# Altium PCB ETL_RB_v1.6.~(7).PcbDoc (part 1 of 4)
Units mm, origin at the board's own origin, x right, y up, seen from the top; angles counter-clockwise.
Board outline 130.3 x 56.5 mm, 8 copper layers (Top Layer, plane 1, M1, plane 2, plane 3, M2, plane 4, Bottom Layer), stack 0.937 mm thick; 215 components, 190 nets, 1969 pads, 914 vias.
Unrouted connection lines stored in the file: 395.
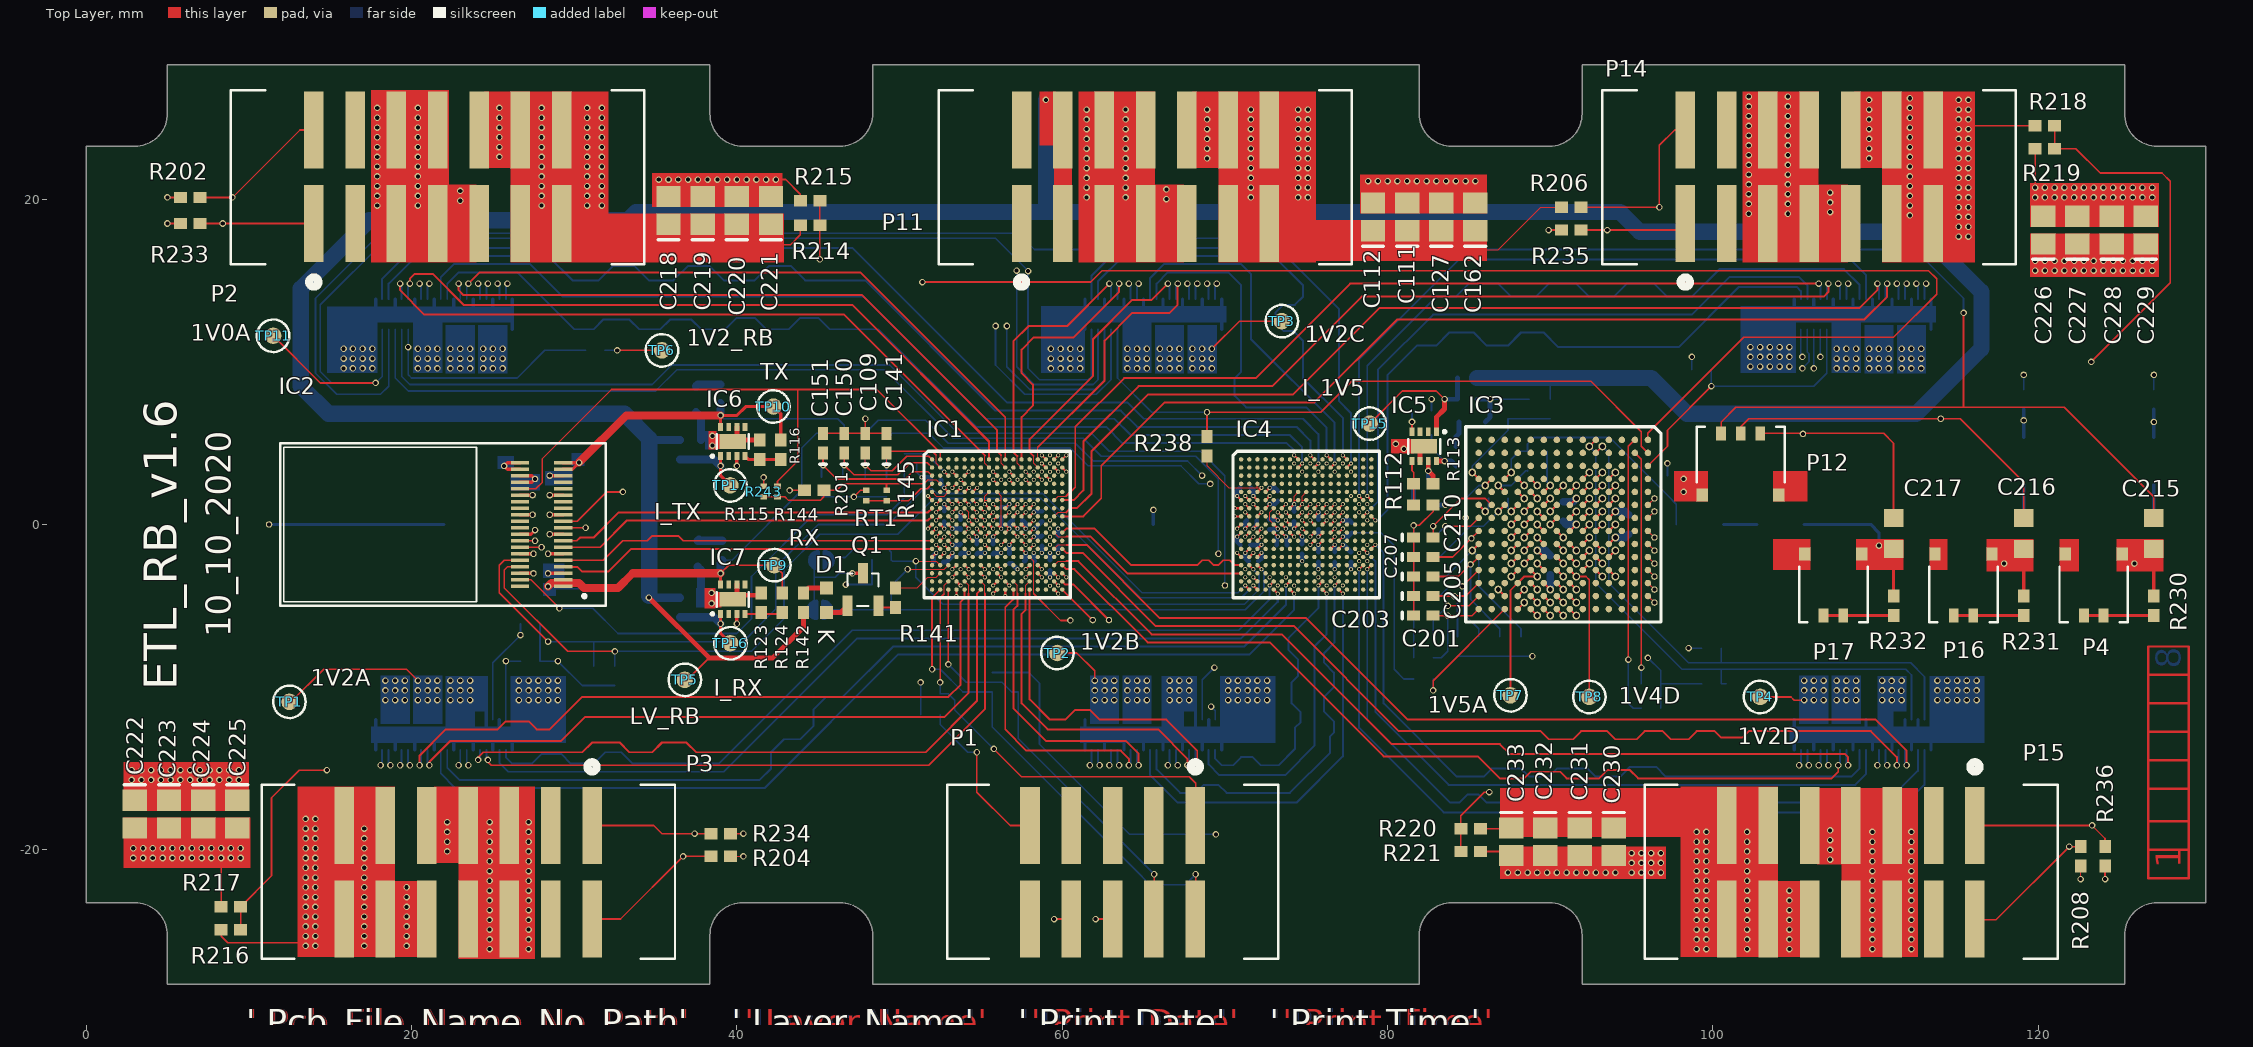
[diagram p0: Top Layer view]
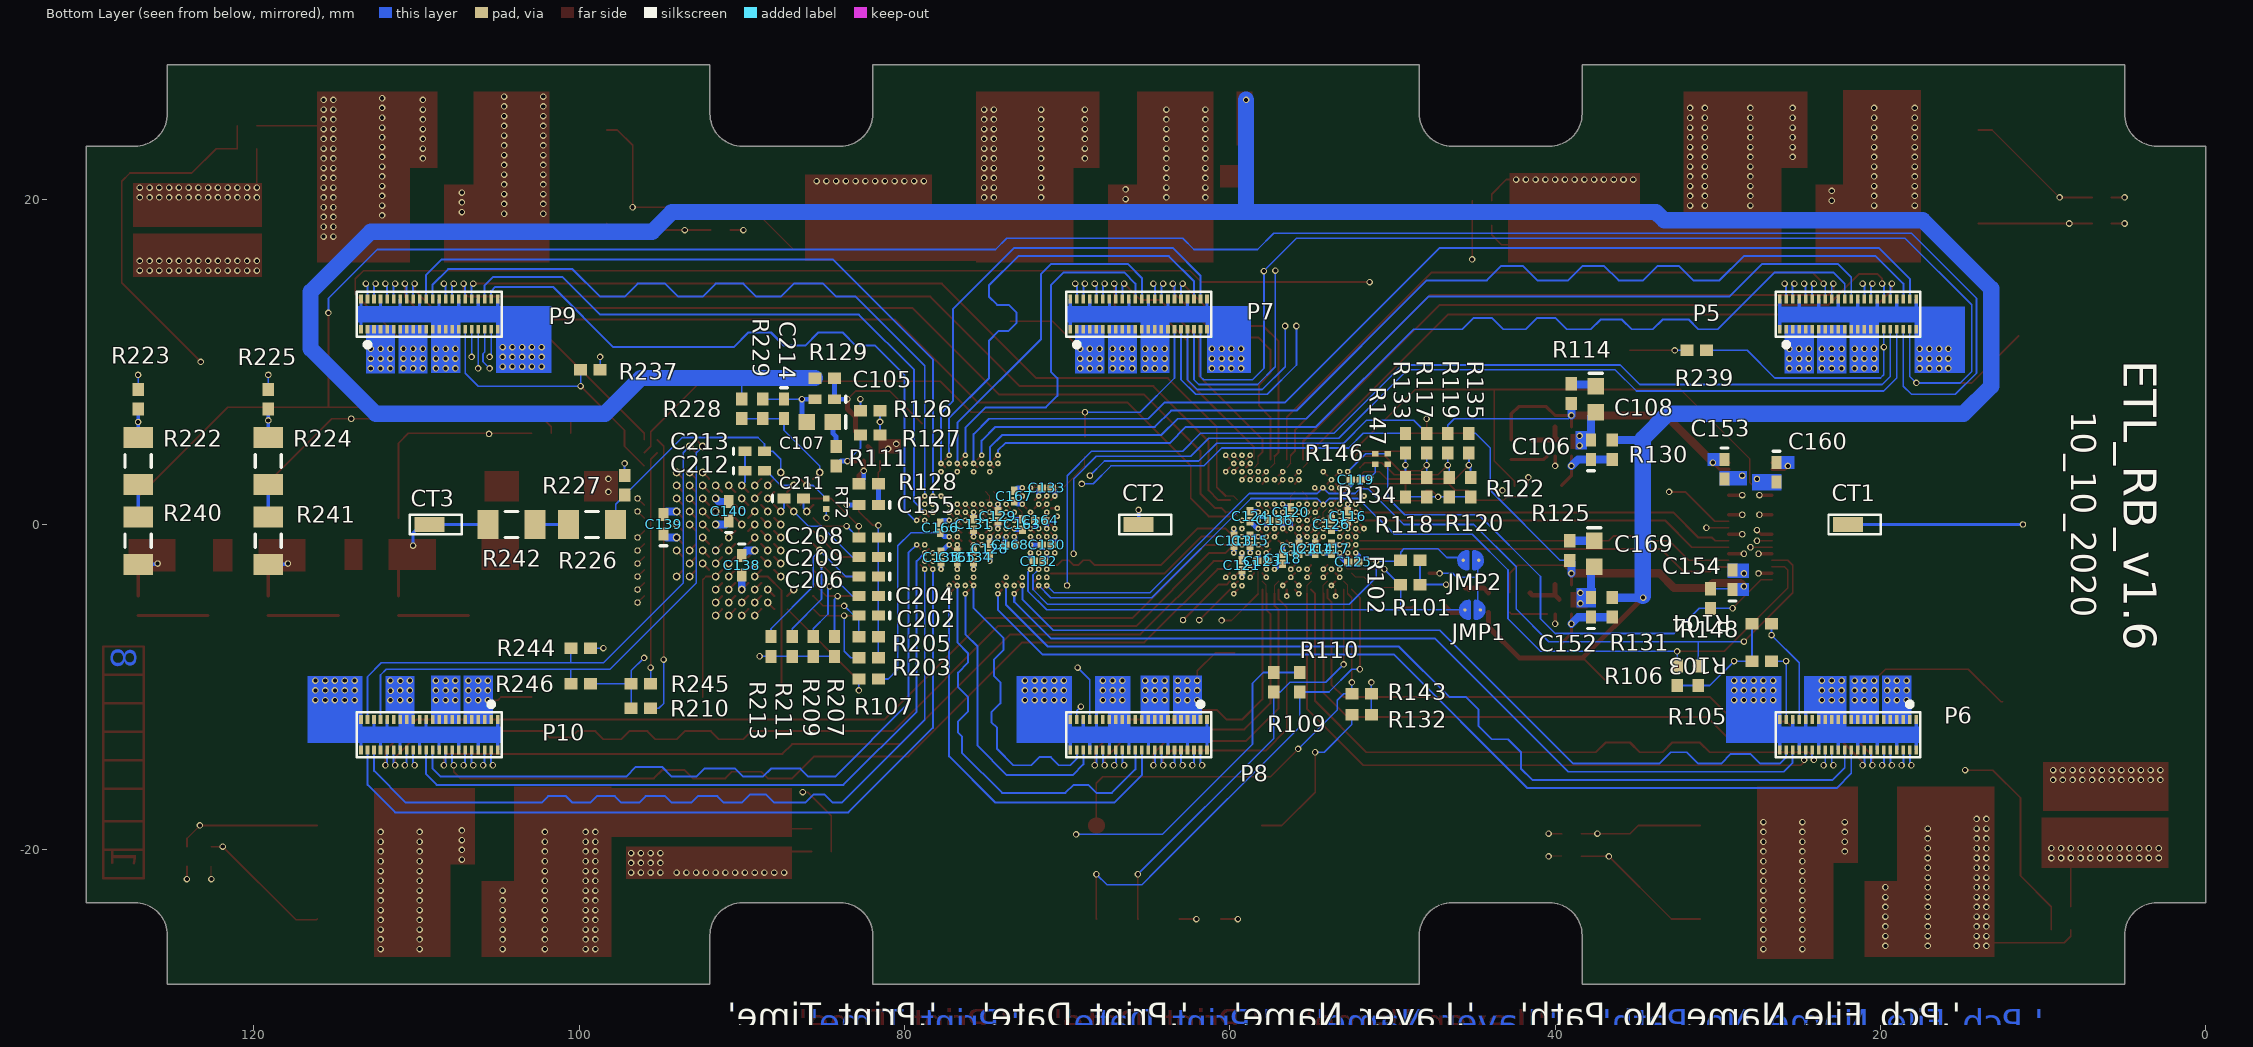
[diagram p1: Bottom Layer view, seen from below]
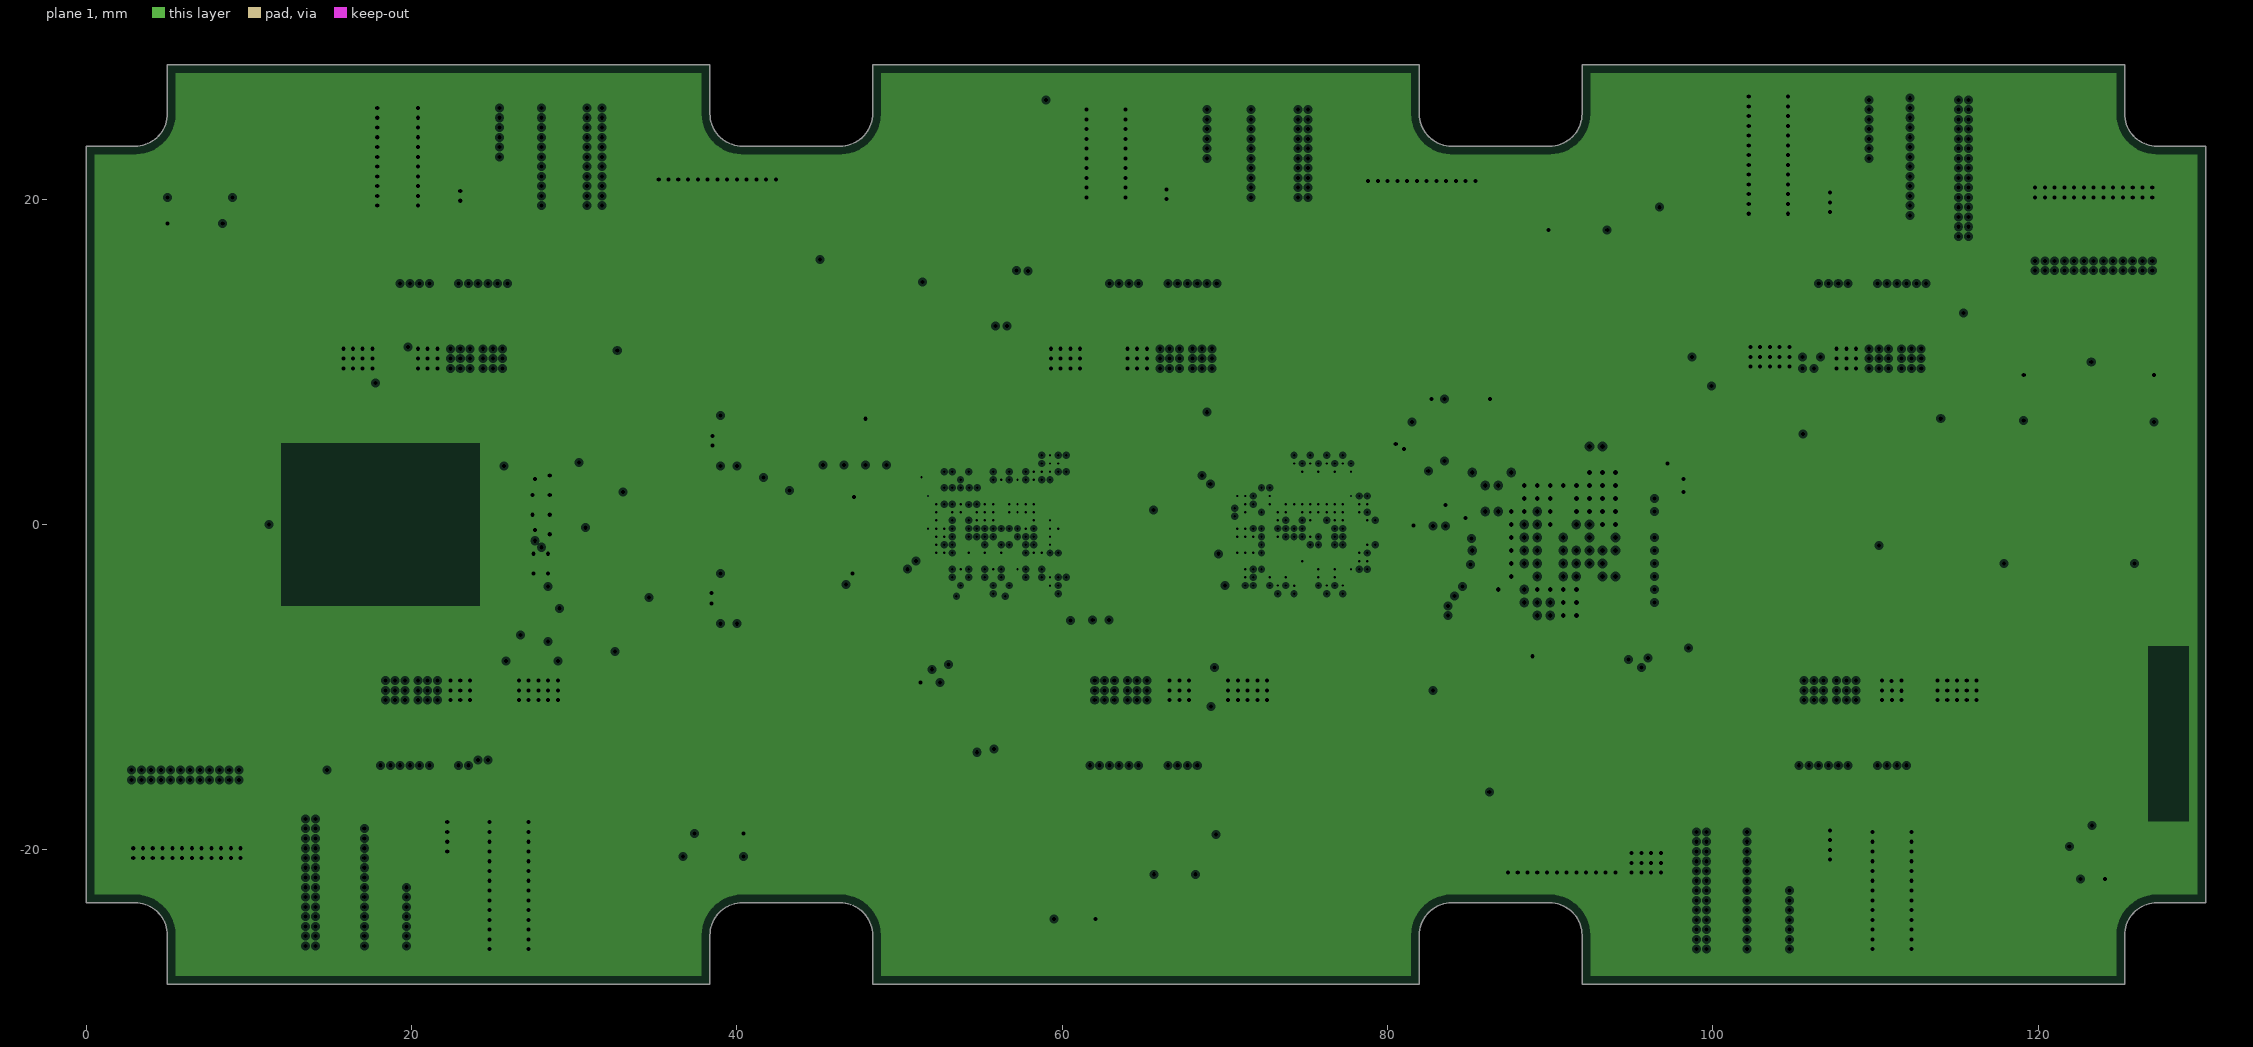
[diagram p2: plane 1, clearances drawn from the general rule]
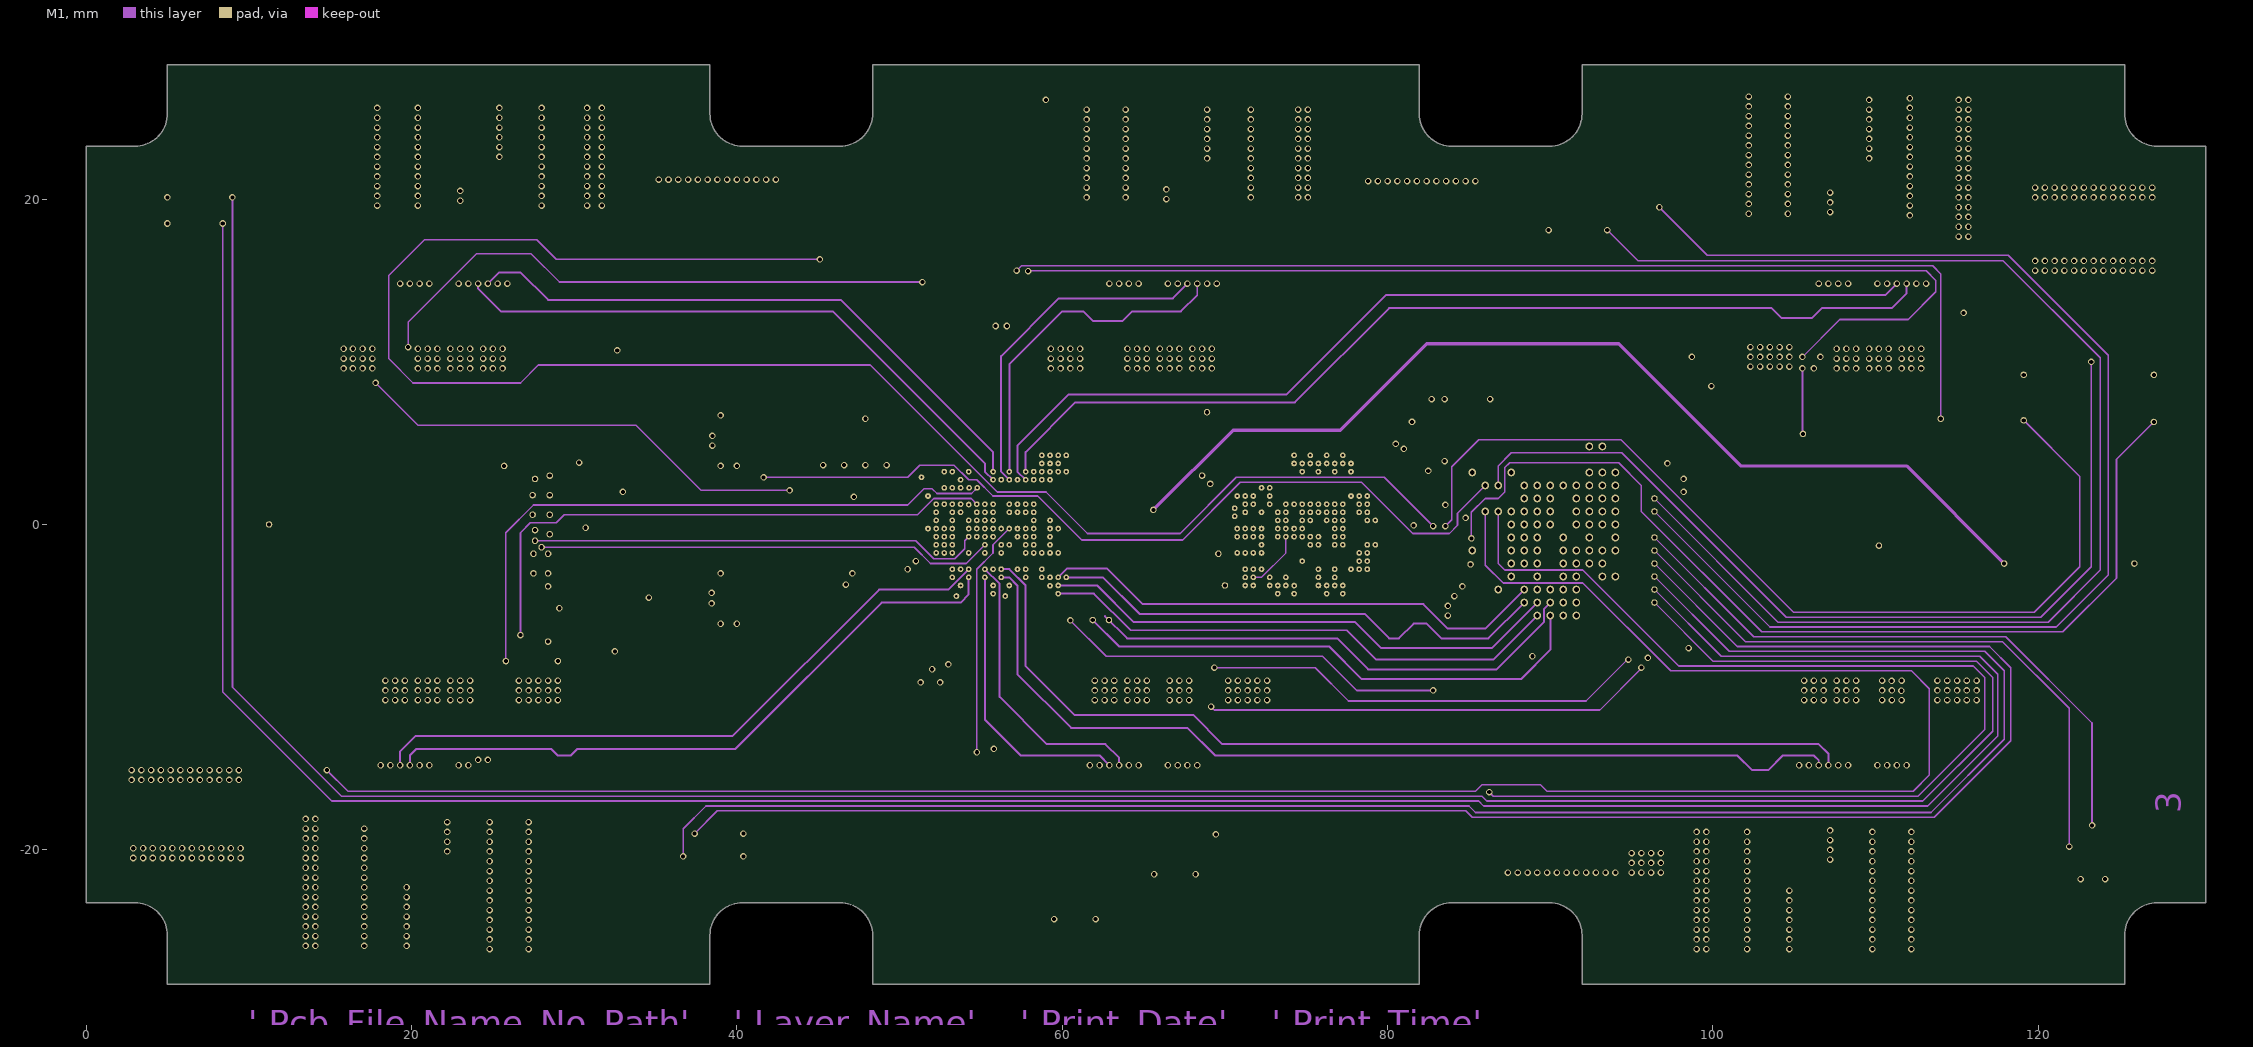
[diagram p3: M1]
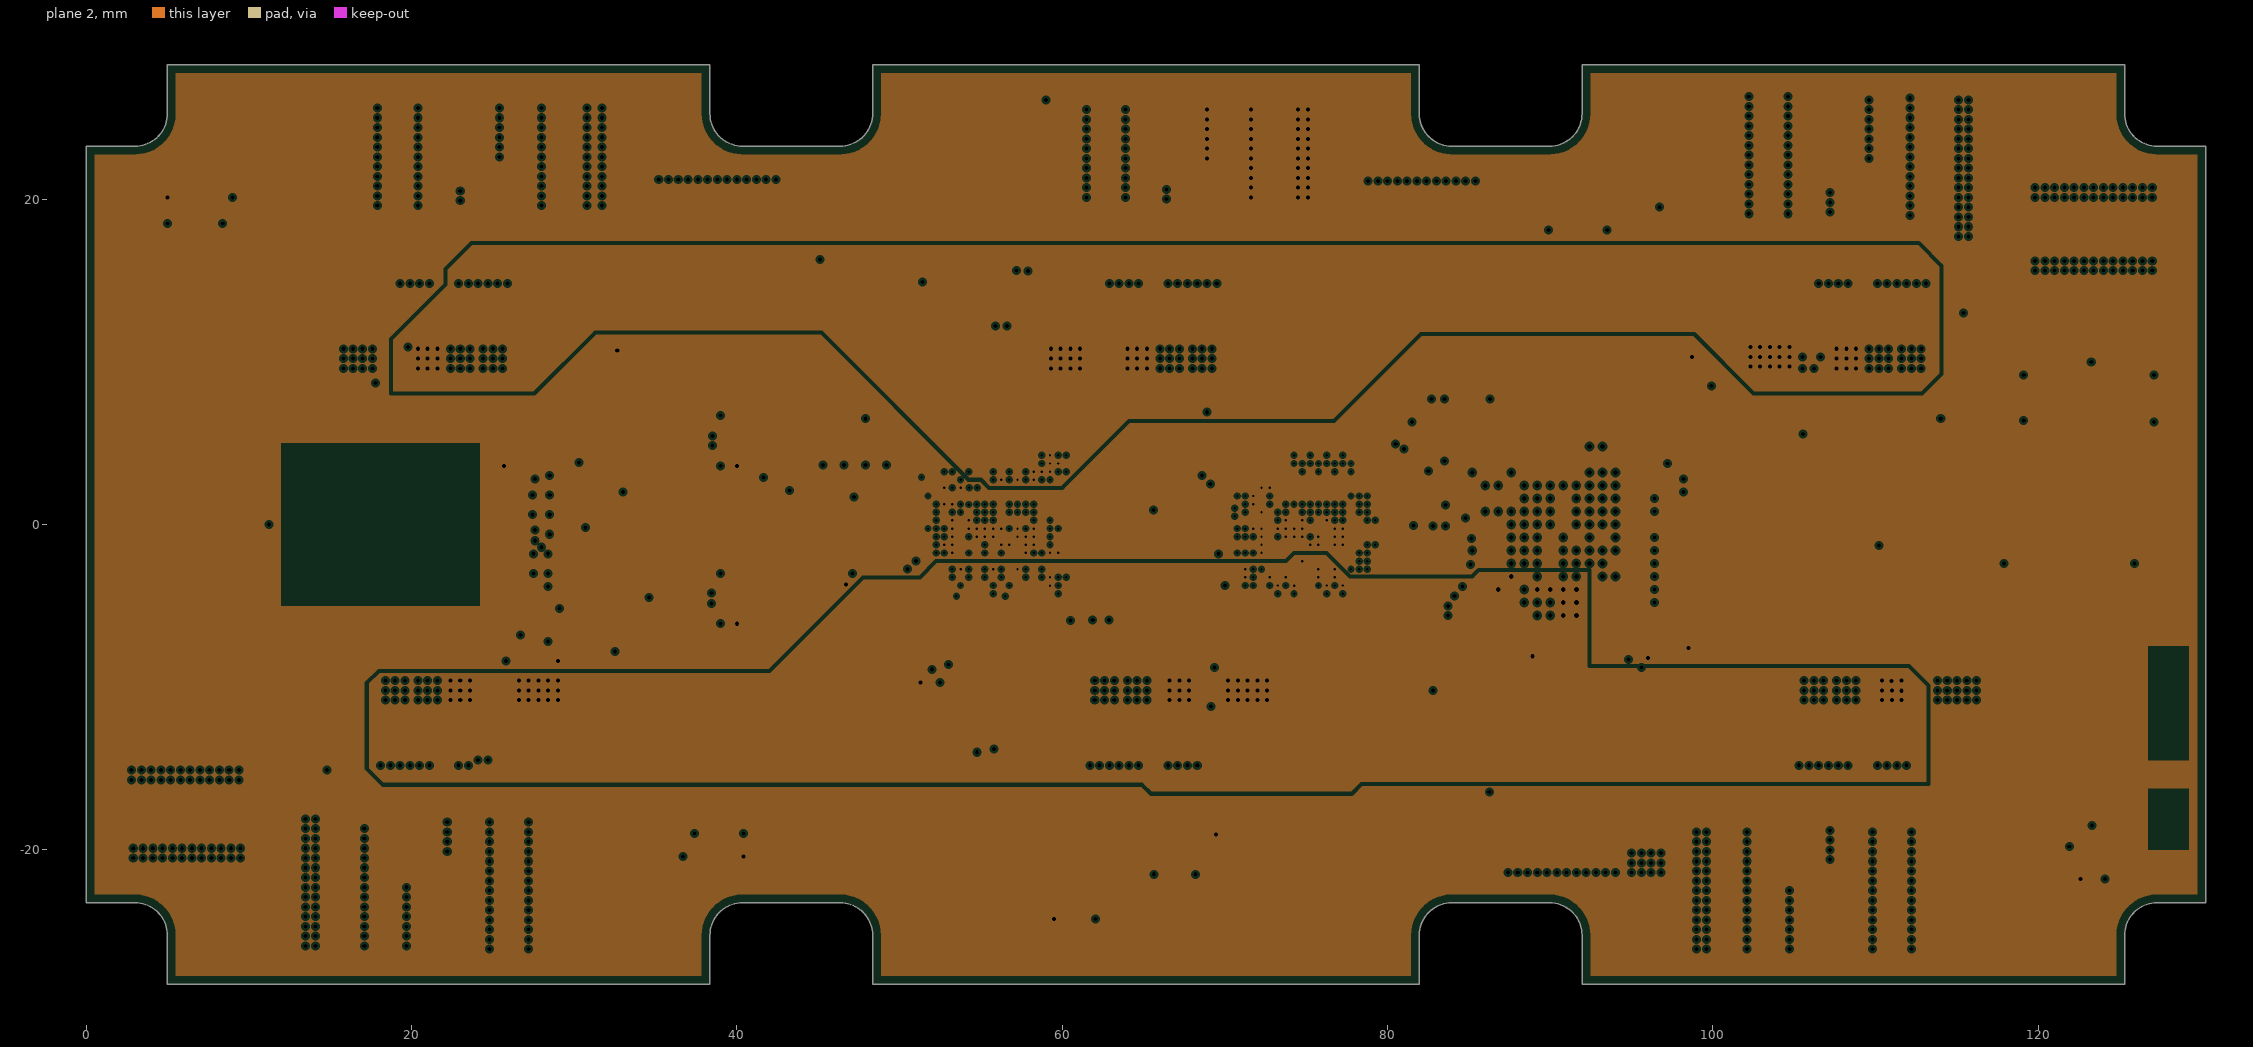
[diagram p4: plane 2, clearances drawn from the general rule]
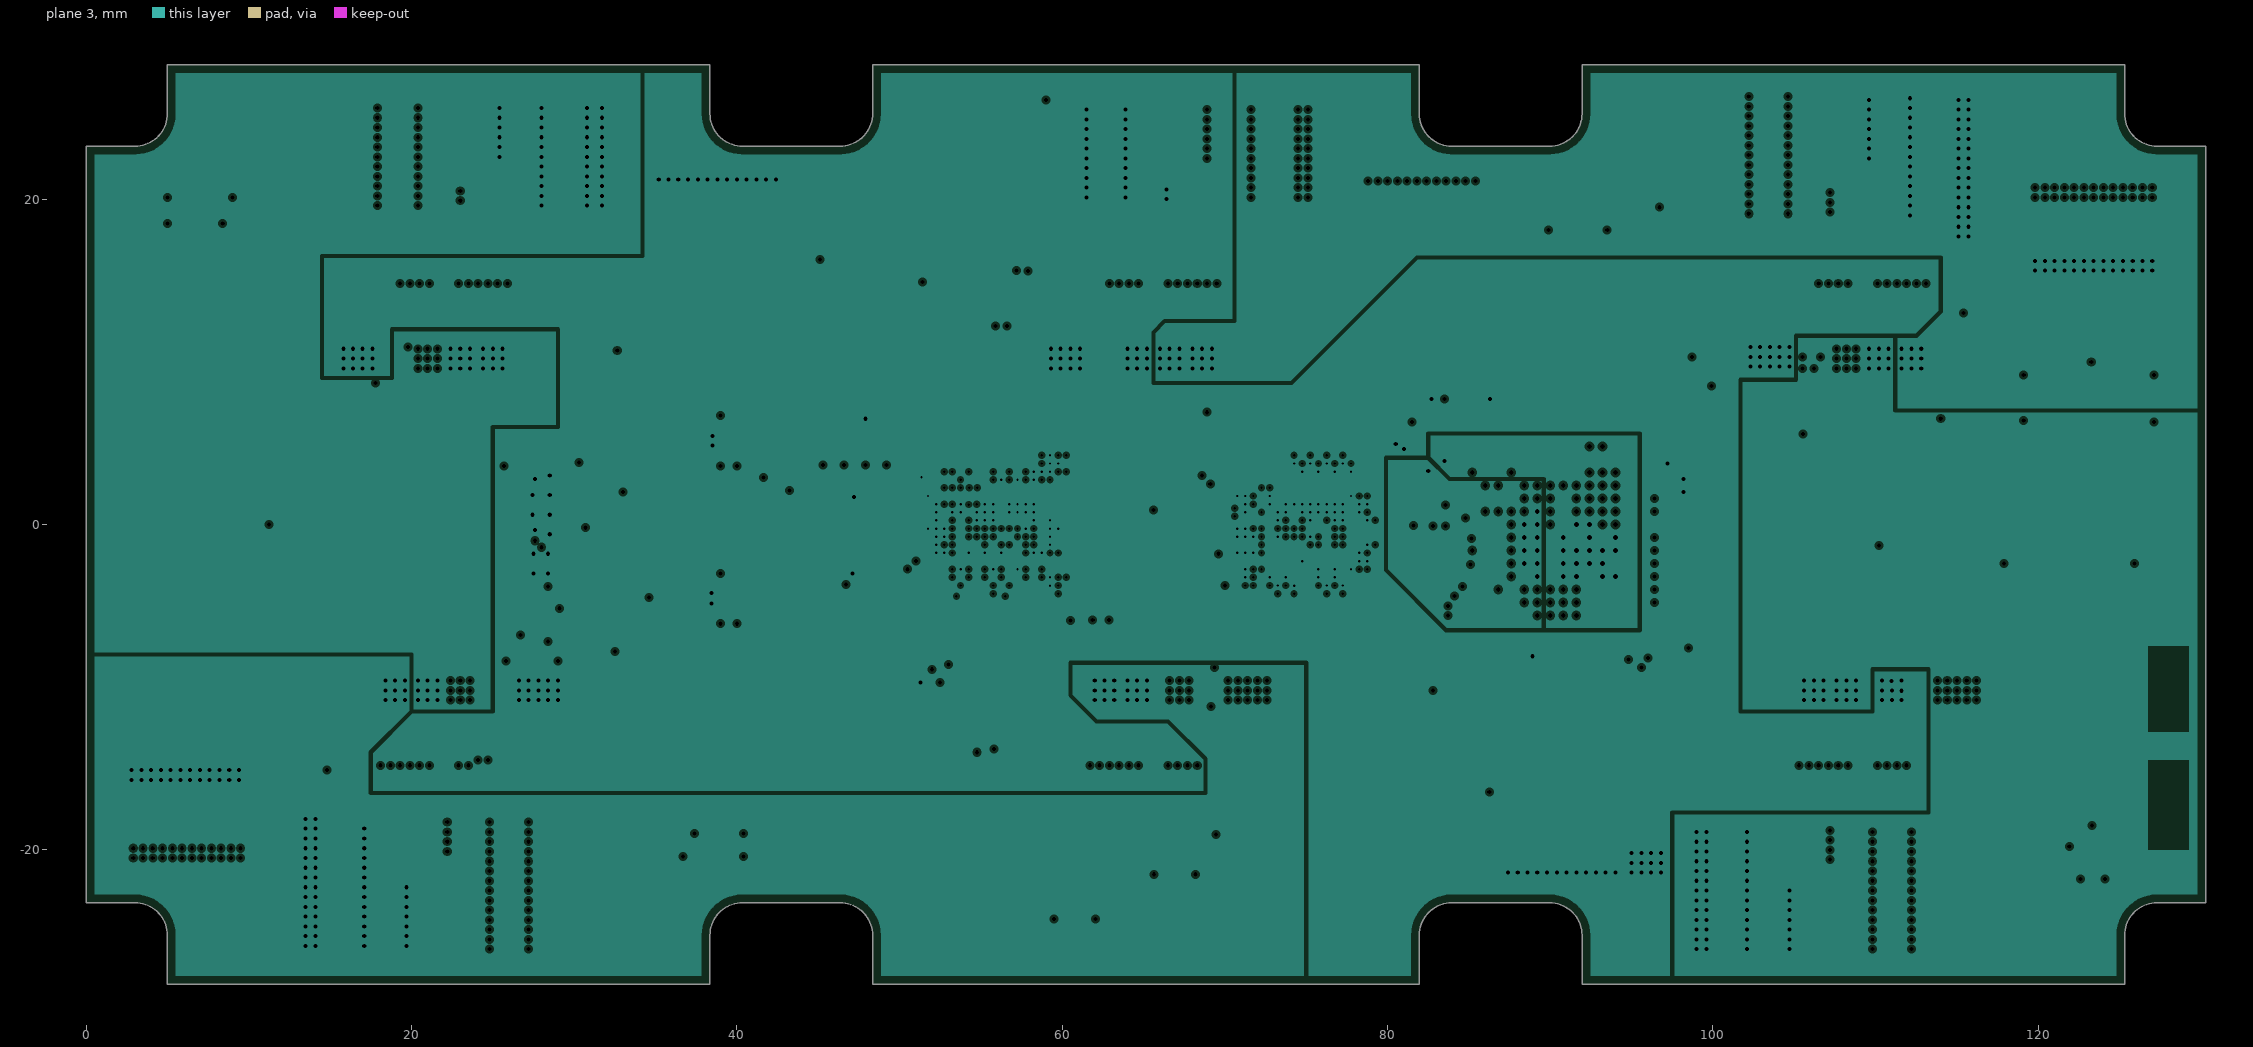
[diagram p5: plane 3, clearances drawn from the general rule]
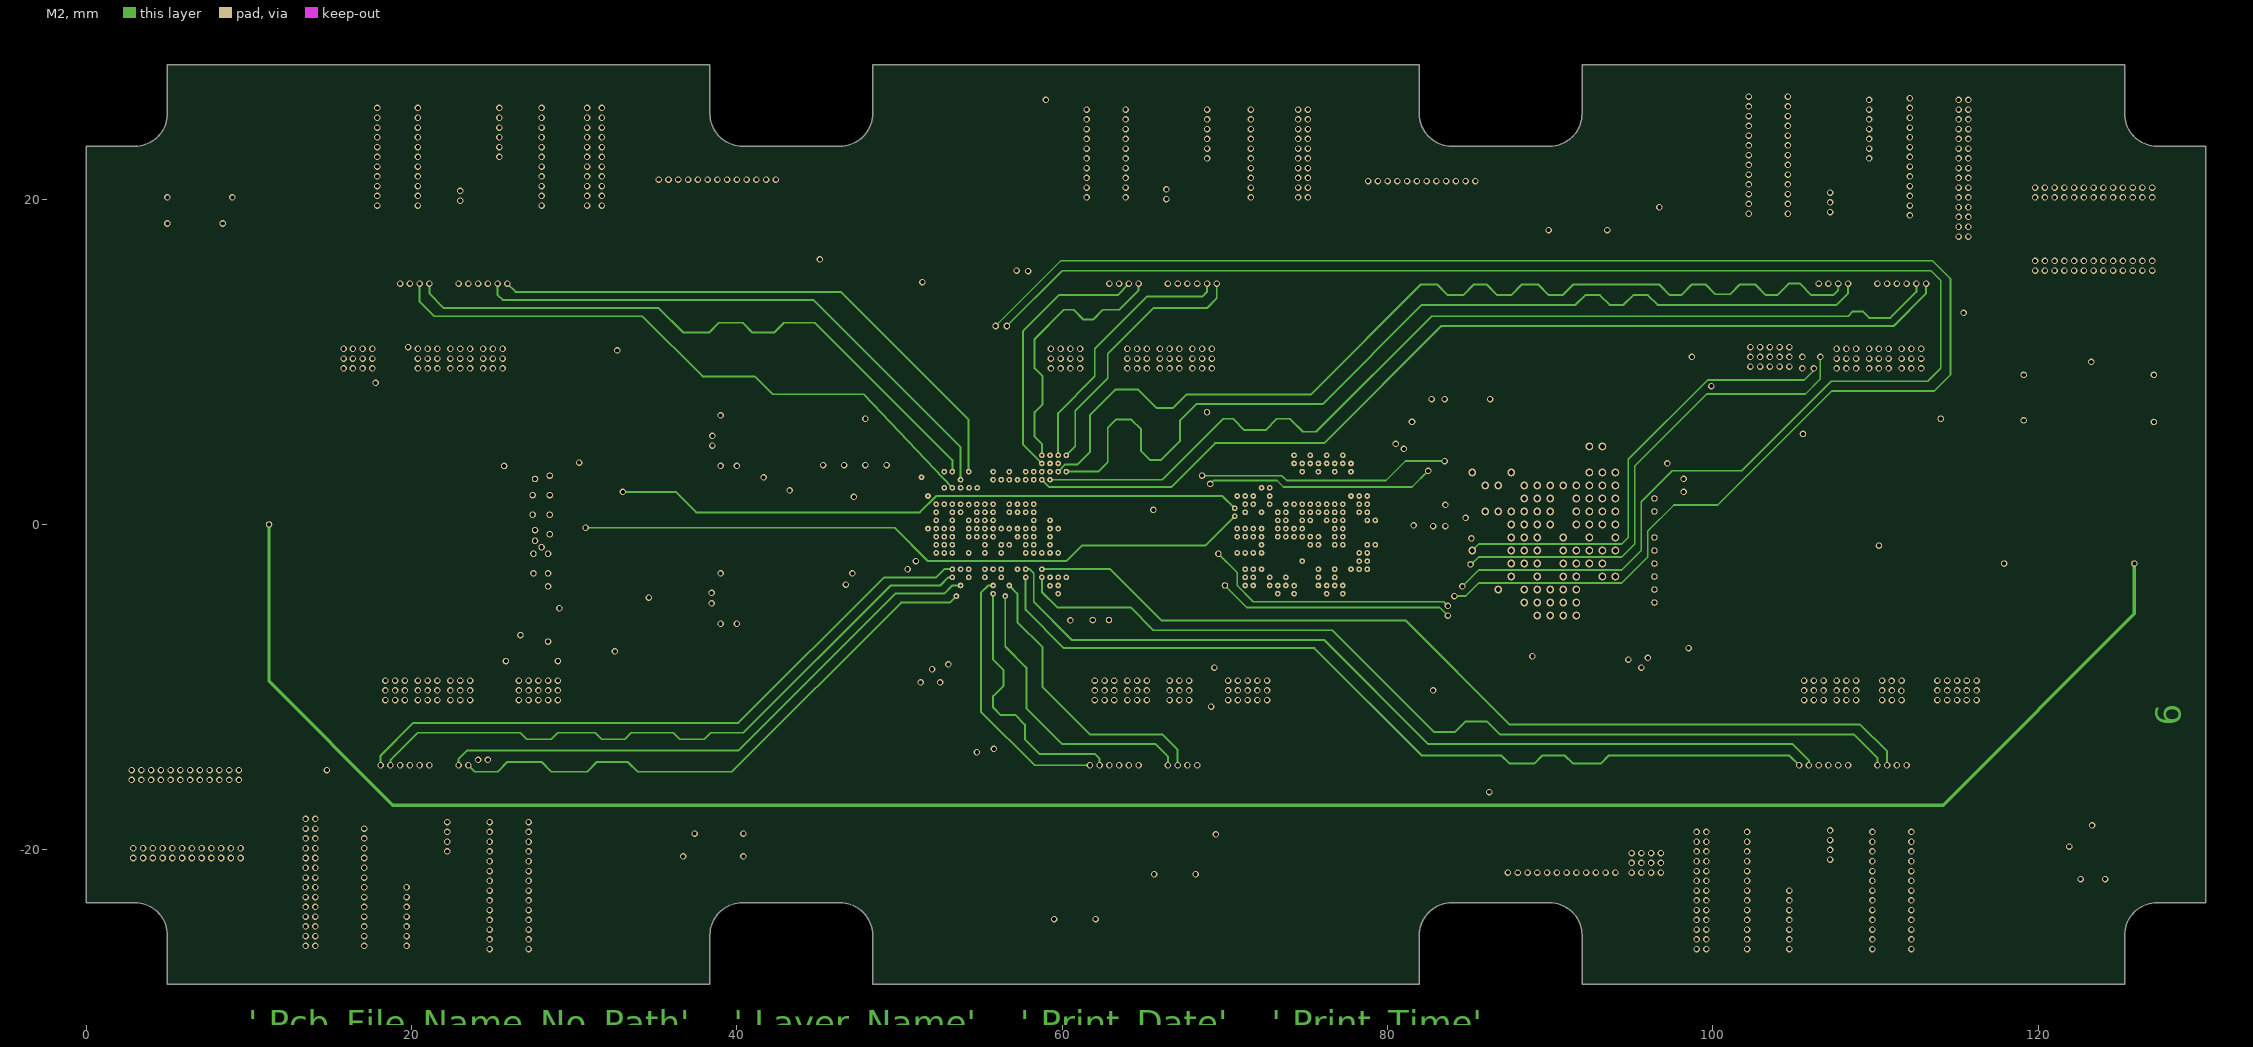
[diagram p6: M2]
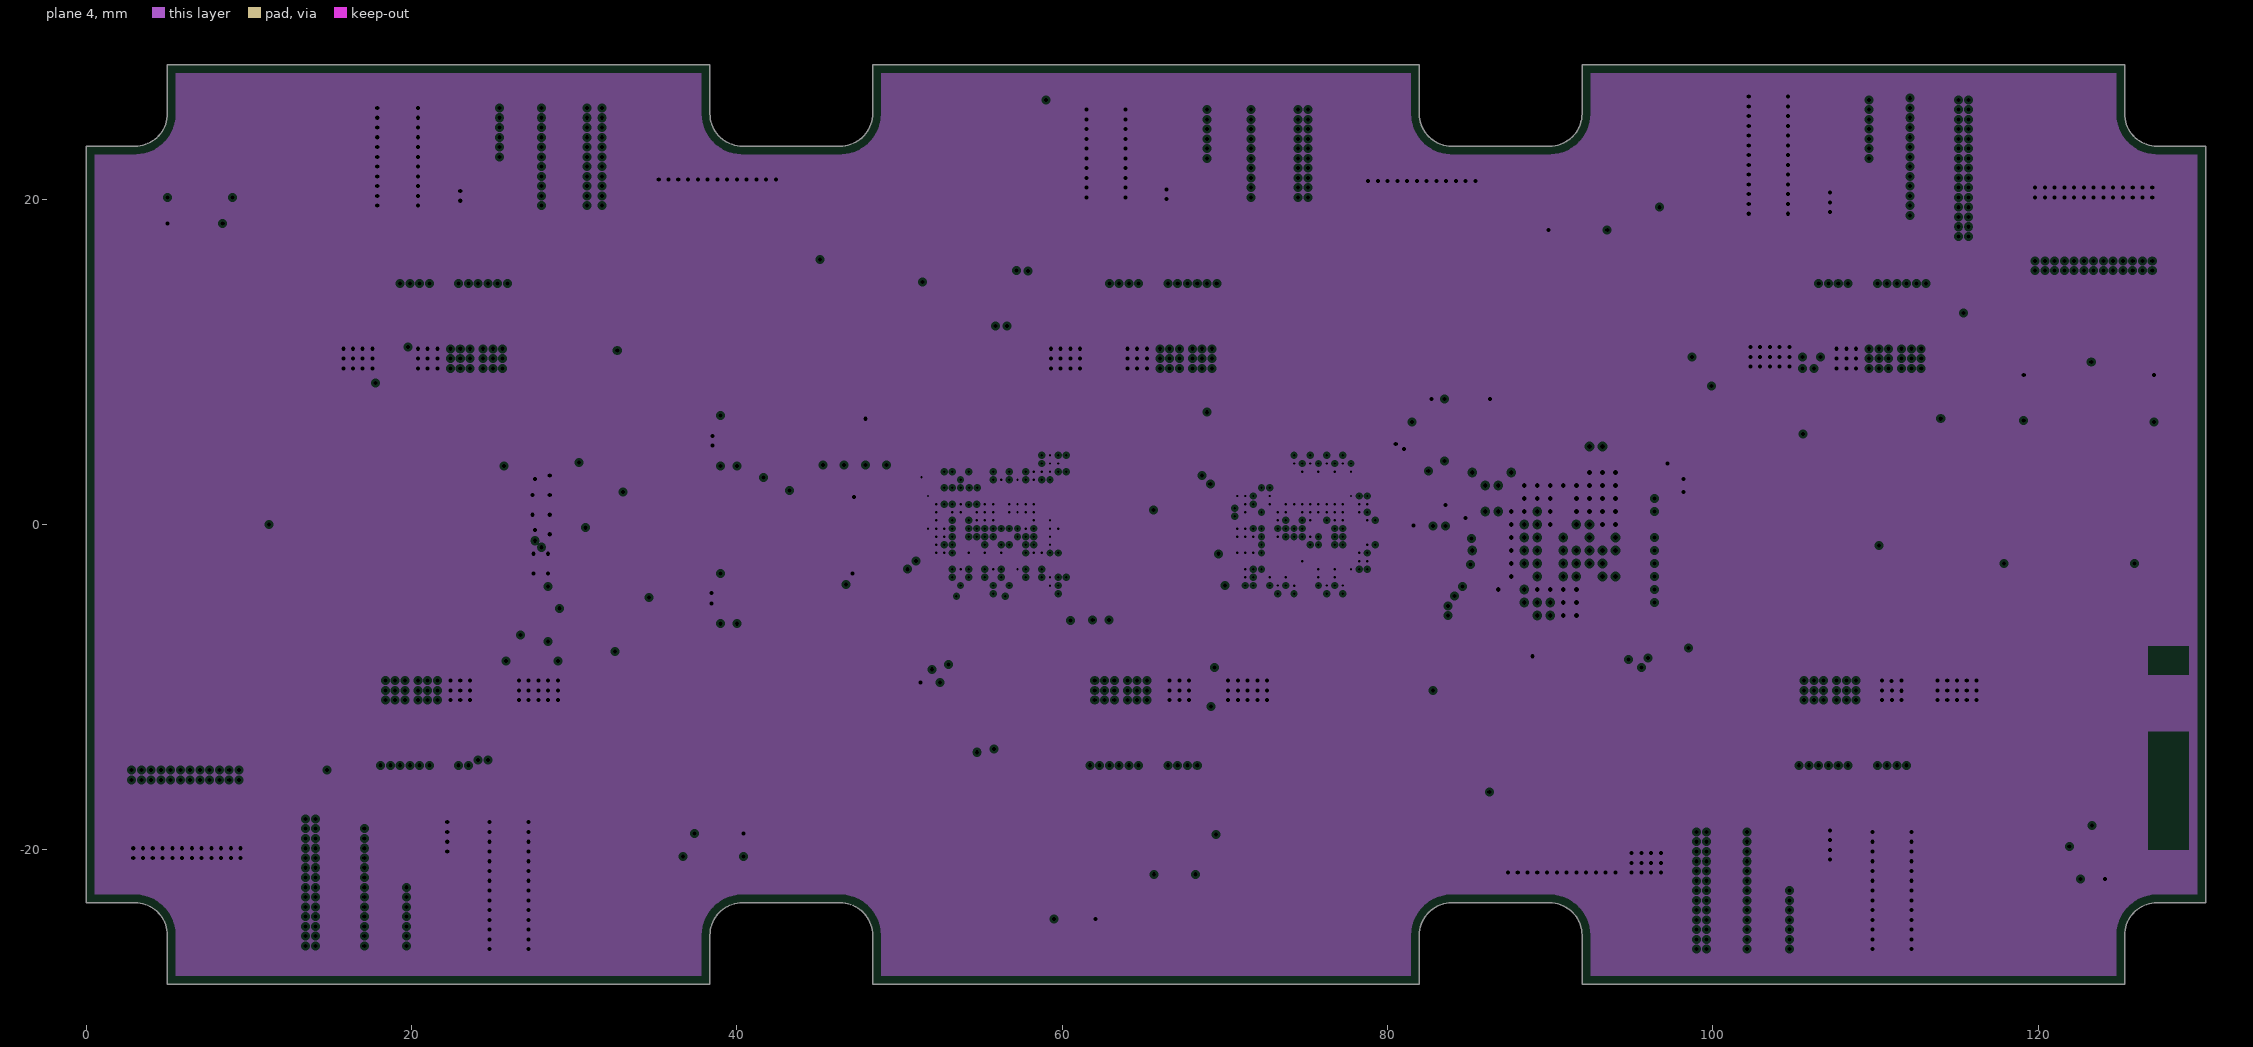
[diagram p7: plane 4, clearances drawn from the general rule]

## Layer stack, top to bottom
Top Solder: solder mask 0.0178, Solder Resist, Dk 4.1
Top Layer: signal copper 0.0175
Dielectric 1: prepreg 0.0691, 1080, Dk 3.4
plane 1: plane copper 0.035, net GND
Dielectric 2: core 0.1016, TU-863, Dk 3.7
M1: signal copper 0.018
Dielectric 3: prepreg 0.1417, 1080, Dk 3.4
plane 2: plane copper 0.035, net (Multiple Nets)
Dielectric 4: core 0.1016, TU-863, Dk 3.7
plane 3: plane copper 0.035, net (Multiple Nets)
Dielectric 5: prepreg 0.1417, 1080, Dk 3.4
M2: signal copper 0.018
Dielectric 6: core 0.1016, TU-863, Dk 3.7
plane 4: plane copper 0.035, net GND
Dielectric 7: prepreg 0.0691, 1080, Dk 3.4
Bottom Layer: signal copper 0.0175
Bottom Solder: solder mask 0.0178, Solder Resist, Dk 4.1

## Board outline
5,-28.25 5,-25.25 ccw(c3,-25.25) 3,-23.25 0,-23.25 0,23.25 3,23.25 ccw(c3,25.25) 5,25.25 5,28.25 38.35,28.25 38.35,25.25 ccw(c40.35,25.25) 40.35,23.25 46.35,23.25 ccw(c46.35,25.25) 48.35,25.25 48.35,28.25 81.95,28.25 81.95,25.25 ccw(c83.95,25.25) 83.95,23.25 89.95,23.25 ccw(c89.95,25.25) 91.95,25.25 91.95,28.25 125.3,28.25 125.3,25.25 ccw(c127.3,25.25) 127.3,23.25 130.3,23.25 130.3,-23.25 127.3,-23.25 ccw(c127.3,-25.25) 125.3,-25.25 125.3,-28.25 91.95,-28.25 91.95,-25.25 ccw(c89.95,-25.25) 89.95,-23.25 83.95,-23.25 ccw(c83.95,-25.25) 81.95,-25.25 81.95,-28.25 48.35,-28.25 48.35,-25.25 ccw(c46.35,-25.25) 46.35,-23.25 40.35,-23.25 ccw(c40.35,-25.25) 38.35,-25.25 38.35,-28.25

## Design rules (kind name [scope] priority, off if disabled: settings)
Clearance [All] p1: gap=0.076 ignorepadtopadclearanceinfootprint=FALSE except(0: Arc-Hole Track-Hole SMDPad-Hole THPad-Hole Via-Hole Fill-Hole Poly-Hole Region-Hole Text-Hole)
Height [All] p1 off: minheight=0 maxheight=25.4 prefheight=12.7
HoleToHoleClearance HoleToHoleClearance_1 [InNet('GND') or InNet('LV_RB') or InNet('1V5A') or InNet('1V5D') or InNet('1V2A') or InNet('1V2B') or InNet('1V2C') or InNet('1V2D') vs InNet('GND') or InNet('LV_RB') or InNet('1V5A') or InNet('1V5D') or InNet('1V2A') or InNet('1V2B') or InNet('1V2C') or InNet('1V2D')] p1: gap=0.15 allowstackedmicrovias=TRUE
HoleToHoleClearance [All] p2: gap=0.254 allowstackedmicrovias=TRUE
MinimumSolderMaskSliver [All] p1: minsoldermaskwidth=0.102
PlaneClearance PlaneClearance_1 [InNetClass('BV')] p1: clearance=0.508
PlaneClearance [All] p2: clearance=0.152
PlaneConnect PlaneConnect_1 [All] p1: planeconnectstyle=Direct reliefexpansion=0.508 reliefentries=4 reliefconductorwidth=0.254 reliefairgap=0.254
PolygonConnect [All] p1: connectstyle=Relief reliefconductorwidth=0.254 reliefentries=4 polygonreliefangle="90 Angle" airgapwidth=0.254
RoomDefinition WP7B [InComponentClass('WP7B')] p1 off: confinementstyle=ConfineIn formatcopy=TRUE lockcomponents=FALSE outline 192.75,16.8 613.75,16.8 613.75,46.8 192.75,46.8
RoomDefinition lpGBT [InComponentClass('lpGBT')] p2 off: confinementstyle=ConfineIn formatcopy=TRUE lockcomponents=FALSE outline 192,-36.75 1047,-36.75 1047,-1.75 192,-1.75
RoutingVias [All] p1: holewidth=0.25 width=0.4 viastyle="Through Hole" minholewidth=0.15 minwidth=0.25 maxholewidth=0.711 maxwidth=1.27
SilkToSilkClearance [All] p1: silktosilkclearance=0.025
SilkToSolderMaskClearance [IsPad] p1: minsilkscreentomaskgap=0.025 clearancetoexposedcopper=TRUE
SolderMaskExpansion SolderMaskExpansion_1 [InPadClass('WP7B40PAD')] p1: expansion=0.038 istentingtop=FALSE
SolderMaskExpansion [All] p2: expansion=0.051 istentingtop=FALSE
Width Width_HS [InNetClass('HS')] p1: maxlimit=0.13 minlimit=0.076 preferedwidth=0.12 midlayer1_minwidth=0.12 midlayer1_maxwidth=0.12 midlayer2_minwidth=0.12 midlayer2_maxwidth=0.12 bottomlayer_minwidth=0.12 bottomlayer_maxwidth=0.12 minimp=50.000000 maximp=50.000000 favimp=50.000000 // impedance controlled signals
Width [All] p2: maxlimit=2.54 minlimit=0.076 preferedwidth=0.12 toplayer_minwidth=0.076 midlayer1_minwidth=0.076 minimp=50.000000 maximp=50.000000 favimp=50.000000
23 further rules are at their usual default settings.

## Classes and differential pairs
pad class WP7B40PAD: IC2-1 IC2-2 IC2-3 IC2-4 IC2-5 IC2-6 IC2-7 IC2-8 IC2-9 IC2-10 IC2-11 IC2-12 IC2-13 IC2-14 IC2-15 IC2-16 IC2-17 IC2-18 IC2-19 IC2-20 IC2-21 IC2-22 IC2-23 IC2-24 IC2-25 IC2-26 IC2-27 IC2-28 IC2-29 IC2-30 IC2-31 IC2-32 IC2-33 IC2-34 IC2-35 IC2-36 IC2-37 IC2-38 IC2-39 IC2-40 IC5-1 IC5-2 IC5-3 IC5-4 IC5-5 IC5-6 IC5-7 IC5-8 IC5-9 IC6-1 IC6-2 IC6-3 IC6-4 IC6-5 IC6-6 IC6-7 IC6-8 IC6-9 IC7-1 IC7-2 IC7-3 IC7-4 IC7-5 IC7-6 IC7-7 IC7-8 IC7-9 P5-1 P5-2 P5-3 P5-4 P5-5 P5-6 P5-7 P5-8 P5-9 P5-10 P5-11 P5-12 P5-13 P5-14 P5-15 P5-16 P5-17 P5-18 P5-19 P5-20 P5-21 P5-22 P5-23 P5-24 P5-25 P5-26 P5-27 P5-28 P5-29 P5-30 P5-31 P5-32 P5-33 P5-34 P5-35 P5-36 P5-37 P5-38 P5-39 P5-40 P5-41 P5-42 P5-43 P5-44 P6-1 P6-2 P6-3 P6-4 P6-5 P6-6 P6-7 P6-8 P6-9 P6-10 P6-11 P6-12 P6-13 P6-14 P6-15 P6-16 P6-17 P6-18 P6-19 P6-20 P6-21 P6-22 P6-23 P6-24 P6-25 P6-26 P6-27 P6-28 P6-29 P6-30 P6-31 P6-32 P6-33 P6-34 P6-35 P6-36 P6-37 P6-38 P6-39 P6-40 P6-41 P6-42 P6-43 P6-44 P7-1 P7-2 P7-3 P7-4 P7-5 P7-6 P7-7 P7-8 P7-9 P7-10 P7-11 P7-12 P7-13 P7-14 P7-15 P7-16 P7-17 P7-18 P7-19 P7-20 P7-21 P7-22 P7-23 P7-24 P7-25 P7-26 P7-27 P7-28 P7-29 P7-30 P7-31 P7-32 P7-33 P7-34 P7-35 P7-36 P7-37 P7-38 P7-39 P7-40 P7-41 P7-42 P7-43 P7-44 P8-1 P8-2 P8-3 P8-4 P8-5 P8-6 P8-7 P8-8 P8-9 P8-10 P8-11 P8-12 P8-13 P8-14 P8-15 P8-16 P8-17 P8-18 P8-19 P8-20 P8-21 P8-22 P8-23 P8-24 P8-25 P8-26 P8-27 P8-28 P8-29 P8-30 P8-31 P8-32 P8-33 P8-34 P8-35 P8-36 P8-37 P8-38 P8-39 P8-40 P8-41 P8-42 P8-43 P8-44 P9-1 P9-2 P9-3 P9-4 P9-5 P9-6 P9-7 P9-8 P9-9 P9-10 P9-11 P9-12 P9-13 P9-14 P9-15 P9-16 P9-17 P9-18 P9-19 P9-20 P9-21 P9-22 P9-23 P9-24 P9-25 P9-26 P9-27 P9-28 P9-29 P9-30 P9-31 P9-32 P9-33 P9-34 P9-35 P9-36 P9-37 P9-38 P9-39 P9-40 P9-41 P9-42 P9-43 P9-44 P10-1 P10-2 P10-3 P10-4 P10-5 P10-6 P10-7 P10-8 P10-9 P10-10 P10-11 P10-12 P10-13 P10-14 P10-15 P10-16 P10-17 P10-18 P10-19 P10-20 P10-21 P10-22 P10-23 P10-24 P10-25 P10-26 P10-27 P10-28 P10-29 P10-30 P10-31 P10-32 P10-33 P10-34 P10-35 P10-36 P10-37 P10-38 P10-39 P10-40 P10-41 P10-42 P10-43 P10-44
component class WP7B: C201 C202 C203 C204 C205 C206 C207 C208 C209 C210 C211 C212 C213 C214 C215 C216 C217 C218 C219 C220 C221 C222 C223 C224 C225 C226 C227 C228 C229 C230 C231 C232 C233 CT1 CT2 CT3 P2 P3 P4 P5 P6 P7 P8 P9 P10 P12 P14 P15 P16 P17 R201 R202 R203 R204 R205 R206 R207 R208 R209 R210 R214 R215 R216 R217 R218 R219 R220 R221 R222 R223 R224 R225 R226 R227 R228 R229 R230 R231 R232 R233 R234 R235 R236 R237 R238 R239 R240 R241 R242 R243 R244 R245 R246 RT2 TP1 TP2 TP3 TP4 TP5 TP6 TP7 TP8 TP9 TP10 TP11
component class lpGBT: C105 C106 C107 C108 C109 C111 C112 C113 C114 C115 C116 C117 C118 C119 C120 C121 C122 C123 C124 C125 C126 C127 C128 C129 C130 C131 C132 C133 C134 C135 C136 C138 C139 C140 C141 C150 C151 C152 C153 C154 C155 C160 C162 C163 C164 C165 C166 C167 C168 C169 D1 IC1 IC2 IC3 IC4 IC5 IC6 IC7 JMP1 JMP2 P1 P11 Q1 R101 R102 R103 R104 R105 R106 R107 R109 R110 R111 R112 R113 R114 R115 R116 R117 R118 R119 R120 R122 R123 R124 R125 R126 R127 R128 R129 R130 R131 R132 R133 R134 R135 R141 R142 R143 R144 R145 R146 R147 R148 RT1 TP15 TP16 TP17

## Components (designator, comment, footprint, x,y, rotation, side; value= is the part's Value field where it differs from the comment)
C105 "GRM155R71E104ME14D" capc1005n 84.9,7.7 r0 bottom value=0.1uF
C106 "GRM155R71E104ME14D" capc1005n 37.8,4.6 r90 bottom value=0.1uF
C107 "GRM185R60J106ME15J" CAPC1608N 85.2,6.3 r0 bottom value=10uF
C108 "GRM185R60J106ME15J" CAPC1608N 37.5,7.7 r270 bottom value=10uF
C109 "GRM155R71E104ME14D" capc1005n 47.9,5 r90 top value=0.1uF
C111 "GRM188R60J476ME15D" capc2012n 81.2,18.9 r90 top value=47uF
C112 "GRM188R60J476ME15D" capc2012n 79.1,18.9 r90 top value=47uF
C113 "GRM033R61C104KE84D" CAPC0603N 59.75,-1 r90 bottom value=0.1uF
C114 "GRM033R61C104KE84D" CAPC0603N 54.75,-1.5 r270 bottom value=0.1uF
C115 "GRM033R61C104KE84D" CAPC0603N 58.75,-1 r270 bottom value=0.1uF
C116 "GRM033R61C104KE84D" CAPC0603N 52.75,0.5 r270 bottom value=0.1uF
C117 "GRM033R61C104KE84D" CAPC0603N 53.75,-1.5 r270 bottom value=0.1uF
C118 "GRM033R61C104KE84D" CAPC0603N 56.75,-2.1 r270 bottom value=0.1uF
C119 "GRM033R61C104KE84D" CAPC0603N 52.25,2.75 r180 bottom value=0.1uF
C120 "GRM033R61C104KE84D" CAPC0603N 56.25,0.75 r90 bottom value=0.1uF
C121 "GRM033R61C104KE84D" CAPC0603N 59.25,-2.5 r270 bottom value=0.1uF
C122 "GRM033R61C153KE84D" CAPC0603N 55.75,-1.5 r270 bottom value=15nF
C123 "GRM033R61C153KE84D" CAPC0603N 58,-2.25 r0 bottom value=15nF
C124 "GRM033R61C153KE84D" CAPC0603N 58.75,0.5 r90 bottom value=15nF
C125 "GRM033R61C153KE84D" CAPC0603N 52.4,-2.3 r180 bottom value=15nF
C126 "GRM033R61C153KE84D" CAPC0603N 53.75,0 r90 bottom value=15nF
C127 "GRM188R60J476ME15D" capc2012n 83.3,18.9 r90 top value=47uF
C128 "GRM033R61C104KE84D" CAPC0603N 74.75,-1.5 r270 bottom value=0.1uF
C129 "GRM033R61C104KE84D" CAPC0603N 74.25,0.5 r90 bottom value=0.1uF
C130 "GRM033R61C104KE84D" CAPC0603N 71.25,-1.25 r180 bottom value=0.1uF
C131 "GRM033R61C104KE84D" CAPC0603N 75.75,0 r90 bottom value=0.1uF
C132 "GRM033R61C104KE84D" CAPC0603N 71.75,-2.25 r180 bottom value=0.1uF
C133 "GRM033R61C104KE84D" CAPC0603N 71.25,2.25 r180 bottom value=0.1uF
C134 "GRM033R61C104KE84D" CAPC0603N 75.75,-2 r270 bottom value=0.1uF
C135 "GRM033R61C104KE84D" CAPC0603N 77.75,-2 r270 bottom value=0.1uF
C136 "GRM033R61C104KE84D" CAPC0603N 57.25,0.25 r0 bottom value=0.1uF
C138 "GRM155R71E104ME14D" capc1005n 90,-2.5 r270 bottom value=0.1uF
C139 "GRM155R71E104ME14D" capc1005n 94.8,0 r90 bottom value=0.1uF
C140 "GRM155R71E104ME14D" capc1005n 90.8,0.8 r90 bottom value=0.1uF
C141 "GRM155R71E104ME14D" capc1005n 49.2,5 r90 top value=0.1uF
C150 "GRM155R71E104ME14D" capc1005n 46.6,5 r90 top value=0.1uF
C151 "GRM155R71E104ME14D" capc1005n 45.3,5 r90 top value=0.1uF
C152 "GRM155R71E104ME14D" capc1005n 37.8,-5.1 r90 bottom value=0.1uF
C153 "GRM155R71E104ME14D" capc1005n 29.6,3.4 r270 bottom value=0.1uF
C154 "GRM155R71E104ME14D" capc1005n 29.1,-3.4 r90 bottom value=0.1uF
C155 "GRM153R60J475ME15D" capc1005n 82.2,1.2 r0 bottom value=4.7uF
C160 "GRM155R71E104ME14D" CAPC1005N 26.4,3.2 r270 bottom value=0.1uF
C162 "GRM188R60J476ME15D" capc2012n 85.4,18.9 r90 top value=47uF
C163 "GRM033R61C104KE84D" CAPC0603N 72.75,0 r90 bottom value=0.1uF
C164 "GRM033R61C153KE84D" CAPC0603N 71.65,0.25 r180 bottom value=15nF
C165 "GRM033R61C153KE84D" CAPC0603N 76.75,-2 r270 bottom value=15nF
C166 "GRM033R61C153KE84D" CAPC0603N 77.8,-0.2 r90 bottom value=15nF
C167 "GRM033R61C153KE84D" CAPC0603N 73.25,1.75 r270 bottom value=15nF
C168 "GRM033R61C153KE84D" CAPC0603N 73.5,-1.25 r180 bottom value=15nF
C169 "GRM185R60J106ME15J" CAPC1608N 37.6,-1.8 r270 bottom value=10uF
C201 "GRM155R71E104ME14D" capc1005n 82.2,-5.6 r0 top value=0.1uF
C202 "GRM155R71E104ME14D" capc1005n 82.2,-5.6 r0 bottom value=0.1uF
C203 "GRM155R71E104ME14D" capc1005n 82.2,-4.4 r0 top value=0.1uF
C204 "GRM155R71E104ME14D" capc1005n 82.2,-4.4 r0 bottom value=0.1uF
C205 "GRM155R71E104ME14D" capc1005n 82.2,-3.2 r0 top value=0.1uF
C206 "GRM155R71E104ME14D" capc1005n 82.2,-3.2 r0 bottom value=0.1uF
C207 "GRM155R71E104ME14D" capc1005n 82.2,-2 r0 top value=0.1uF
C208 "GRM155R71E104ME14D" capc1005n 82.2,-0.8 r0 bottom value=0.1uF
C209 "GRM155R71E104ME14D" capc1005n 82.2,-2 r0 bottom value=0.1uF
C210 "GRM155R71E104ME14D" capc1005n 82.2,-0.8 r0 top value=0.1uF
C211 "GRM155R71E104ME14D" capc1005n 86.8,1.6 r180 bottom value=0.1uF
C212 "GRM155R71E104ME14D" capc1005n 89.2,3.3 r180 bottom value=0.1uF
C213 "GRM155R71E104ME14D" capc1005n 89.2,4.5 r180 bottom value=0.1uF
C214 "GRM155R71E104ME14D" capc1005n 87.4,7.1 r270 bottom value=0.1uF
C215 "C0805X7R102-152MNE" VENKEL0805 127.1,-1.5 r90 top value=1500pF
C216 "C0805X7R102-152MNE" VENKEL0805 119.1,-1.5 r90 top value=1500pF
C217 "C0805X7R102-152MNE" VENKEL0805 111.1,-1.5 r90 top value=1500pF
C218 "GRM188R60J476ME15D" capc2012n 35.8,19.3 r90 top value=47uF
C219 "GRM188R60J476ME15D" capc2012n 37.9,19.3 r90 top value=47uF
C220 "GRM188R60J476ME15D" capc2012n 40,19.3 r90 top value=47uF
C221 "GRM188R60J476ME15D" capc2012n 42.1,19.3 r90 top value=47uF
C222 "GRM188R60J476ME15D" capc2012n 3,-17.8 r270 top value=47uF
C223 "GRM188R60J476ME15D" capc2012n 5.1,-17.8 r270 top value=47uF
C224 "GRM188R60J476ME15D" capc2012n 7.2,-17.8 r270 top value=47uF
C225 "GRM188R60J476ME15D" capc2012n 9.3,-17.8 r270 top value=47uF
C226 "GRM188R60J476ME15D" capc2012n 120.3,18.1 r90 top value=47uF
C227 "GRM188R60J476ME15D" capc2012n 122.4,18.1 r90 top value=47uF
C228 "GRM188R60J476ME15D" capc2012n 124.5,18.1 r90 top value=47uF
C229 "GRM188R60J476ME15D" capc2012n 126.6,18.1 r90 top value=47uF
C230 "GRM188R60J476ME15D" capc2012n 93.9,-19.5 r270 top value=47uF
C231 "GRM188R60J476ME15D" capc2012n 91.8,-19.5 r270 top value=47uF
C232 "GRM188R60J476ME15D" capc2012n 89.7,-19.5 r270 top value=47uF
C233 "GRM188R60J476ME15D" capc2012n 87.6,-19.5 r270 top value=47uF
CT1 "TE1551631-5" CONTACT 22,0 r0 bottom locked
CT2 "TE1551631-5" CONTACT 65.6,0 r0 bottom locked
CT3 "TE1551631-5" CONTACT 109.2,0 r0 bottom locked
D1 "LTST-C191KGKT" LED_RED 45.5,-3.9 r270 top
IC1 "LPGBT" BGA289X17 52,4 r0 top
IC2 "DF40C-40DS-0.4V" VTRX+ 29.33,-3.8 r90 top locked
IC3 "GBT-SCA" BGA196C80P14X14_1200X1200X170 96,5.2 r270 top
IC4 "LPGBT" BGA289X17 71,4 r0 top
IC5 "linPOL12V" WDFNX208 83,5.7 r180 top
IC6 "linPOL12V" WDFNX208 39,4.2 r0 top
IC7 "linPOL12V" WDFNX208 39,-5.5 r0 top
JMP1 "Not a component, printed on PCB" JMP2PCB#1 45.1,-5.25 r90 bottom
JMP2 "Not a component, printed on PCB" JMP2PCB#2 45.2,-2.2 r90 bottom
P1 "CnC3020-10-0300-00" cnc10 68.18,-18.5 r180 top
P2 "CnC3020-14-0300-00" cnc14 14,18.5 r0 top locked
P3 "CnC3020-14-0300-00" cnc14 31.1,-18.5 r180 top locked
P4 "DF57-2P-1.2V(21)" DF57-2 122.8,-5.6 r0 top
P5 "WP7B-P040VA1" WP7B-40P 25.8,12 r180 bottom locked
P6 "WP7B-P040VA1" WP7B-40P 18.2,-12 r0 bottom locked
P7 "WP7B-P040VA1" WP7B-40P 69.4,12 r180 bottom locked
P8 "WP7B-P040VA1" WP7B-40P 61.8,-12 r0 bottom locked
P9 "WP7B-P040VA1" WP7B-40P 113,12 r180 bottom locked
P10 "WP7B-P040VA1" WP7B-40P 105.4,-12 r0 bottom locked
P11 "CnC3020-14-0300-00" cnc14 57.5,18.5 r0 top locked
P12 "DF57-3P-1.2V(21)" DF57-3 102.9,5.6 r180 top
P14 "CnC3020-14-0300-00" cnc14 98.3,18.5 r0 top locked
P15 "CnC3020-14-0300-00" cnc14 116.1,-18.5 r180 top locked
P16 "DF57-2P-1.2V(21)" DF57-2 114.8,-5.6 r0 top
P17 "DF57-2P-1.2V(21)" DF57-2 106.8,-5.6 r0 top
Q1 "KSC2223YMTF" SOT-23 46.8,-5 r0 top
R101 "ERJ-2GEJ392X" resc1005n 48.9,-3.7 r180 bottom
R102 "ERJ-2GEJ392X" resc1005n 48.9,-2.2 r0 bottom
R103 "ERJ-2GEJ392X" resc1005n 27.3,-8.4 r180 bottom
R104 "ERJ-2GEJ392X" resc1005n 27.3,-6.1 r180 bottom
R105 "ERJ-2GEJ392X" resc1005n 31.2,-9.3 r270 bottom
R106 "ERJ-2GEJ392X" resc1005n 32.5,-9.3 r270 bottom
R107 "ERJ-2GEJ392X" resc1005n 82.2,-9.5 r0 bottom
R109 "ERJ-2GEJ392X" resc1005n 57.3,-9.7 r90 bottom
R110 "ERJ-2GEJ392X" resc1005n 55.7,-9.7 r90 bottom
R111 "ERJ-2BQJR30X" resc1005n 84.2,4.2 r90 bottom
R112 "RR0510P-4020-D" resc1005n 82.2,1.2 r0 top
R113 "RR0510P-6040-D" resc1005n 82.2,2.5 r180 top
R114 "ERJ-2BQJR30X" resc1005n 39,8.05 r270 bottom
R115 "RR0510P-4870-D" resc1005n 41.4,4.6 r90 top
R116 "RR0510P-1541-D" resc1005n 42.7,4.6 r270 top
R117 "RR0510P-152-D" resc1005n 47.9,5 r90 bottom
R118 "RR0510P-202-D" resc1005n 47.9,2.3 r90 bottom
R119 "RR0510P-302-D" resc1005n 46.6,5 r90 bottom
R120 "RR0510P-152-D" resc1005n 46.5,2.3 r90 bottom
R122 "RR0510P-152-D" resc1005n 45.2,2.3 r90 bottom
R123 "RR0510P-4870-D" resc1005n 41.5,-4.8 r90 top
R124 "RR0510P-1541-D" resc1005n 42.8,-4.8 r270 top
R125 "ERJ-2BQJR30X" resc1005n 39.1,-1.6 r270 bottom
R126 "RR0510P-511-D" resc1005n 82.1,7 r0 bottom
R127 "RR0510P-681-D" resc1005n 82.1,5.5 r180 bottom
R128 "ERJ-2BQJR30X" resc1005n 82.2,2.5 r180 bottom
R129 "ERJ-2GEJ5R1X" resc1005n 84.9,9 r180 bottom
R130 "ERJ-2GEJ5R1X" resc1005n 36.5,4.6 r270 bottom
R131 "ERJ-2GEJ5R1X" resc1005n 36.5,-5.1 r270 bottom
R132 "ERJ-2GEJ392X" resc1005n 51.9,-11.7 r180 bottom
R133 "RR0510P-152-D" resc1005n 49.2,5 r90 bottom
R134 "RR0510P-202-D" resc1005n 49.2,2.3 r90 bottom
R135 "RR0510P-302-D" resc1005n 45.3,5 r90 bottom
R141 "ERJ-2GEJ511X" resc1005n 49.75,-4.5 r270 top
R142 "ERJ-2GEJ102X" resc1005n 44.1,-4.8 r90 top
R143 "ERJ-2GEJ392X" resc1005n 51.9,-10.4 r0 bottom
R144 "ERJ-1GNF-1002C" RESC0603 42.5,2.35 r270 top
R145 "ERJ-1GNF-1002C" resc0603 49.2,1.45 r90 top
R146 "ERJ-1GEF4023C" resc0603 51.05,3.7 r90 bottom
R147 "ERJ-1GNF1004C" resc0603 50.3,4.35 r270 bottom
R148 "ERJ-2RKF4751X" resc1005n 30.45,-4.55 r90 bottom
R201 "ERJ-2GEJ201X" resc1005n 44.75,2.1 r0 top
R202 "ERJ-2GEJ392X" resc1005n 6.4,20.1 r180 top
R203 "RR0510P-302-D" resc1005n 82.2,-8.2 r0 bottom
R204 "ERJ-2GEJ392X" resc1005n 39,-20.4 r0 top
R205 "RR0510P-302-D" resc1005n 82.2,-6.9 r0 bottom
R206 "ERJ-2GEJ392X" resc1005n 91.3,19.5 r180 top
R207 "RR0510P-302-D" resc1005n 84.3,-7.5 r90 bottom
R208 "ERJ-2GEJ392X" resc1005n 122.6,-20.4 r270 top
R209 "RR0510P-302-D" resc1005n 85.6,-7.5 r90 bottom
R210 "ERJ-2GEJ392X" resc1005n 96.2,-9.8 r0 bottom
R211 "RR0510P-302-D" resc1005n 86.9,-7.5 r90 bottom
R213 "RR0510P-302-D" resc1005n 88.2,-7.5 r90 bottom
R214 "RR0510P-122-D" resc1005n 44.5,18.4 r180 top
R215 "RR0510P-302-D" resc1005n 44.5,19.9 r0 top
R216 "RR0510P-122-D" resc1005n 8.9,-24.9 r180 top
R217 "RR0510P-302-D" resc1005n 8.9,-23.5 r0 top
R218 "RR0510P-122-D" resc1005n 120.4,24.5 r180 top
R219 "RR0510P-302-D" resc1005n 120.4,23.1 r0 top
R220 "RR0510P-122-D" resc1005n 85.1,-18.7 r0 top
R221 "RR0510P-302-D" resc1005n 85.1,-20.1 r180 top
R222 "HVC1206T5005JET" RESC3216N 127.1,3.9 r270 bottom
R223 "RR0510P-823-D" resc1005n 127.1,7.7 r270 bottom
R224 "HVC1206T5005JET" RESC3216N 119.1,3.9 r270 bottom
R225 "RR0510P-823-D" resc1005n 119.1,7.7 r270 bottom
R226 "HVC1206T5005JET" RESC3216N 99.2,0 r0 bottom
R227 "RR0510P-823-D" resc1005n 97.2,2.4 r270 bottom
R228 "RR0510P-103-D" resc1005n 90,7.1 r90 bottom
R229 "RR0510P-102-D" resc1005n 88.7,7.1 r270 bottom
R230 "ERJ-2GEJ201X" resc1005n 127.1,-5 r270 top
R231 "ERJ-2GEJ201X" resc1005n 119.1,-5 r270 top
R232 "ERJ-2GEJ201X" resc1005n 111.1,-5 r270 top
R233 "ERJ-2GEJ392X" resc1005n 6.4,18.5 r180 top
R234 "ERJ-2GEJ392X" resc1005n 39,-19 r0 top
R235 "ERJ-2GEJ392X" resc1005n 91.3,18.1 r180 top
R236 "ERJ-2GEJ392X" resc1005n 124.1,-20.4 r270 top
R237 "ERJ-2GEJ392X" resc1005n 99.3,9.5 r180 bottom
R238 "ERJ-2GEJ392X" resc1005n 68.9,4.8 r270 top
R239 "ERJ-2GEJ392X" resc1005n 31.3,10.7 r0 bottom
R240 "HVC1206T5005JET" RESC3216N 127.1,-1 r270 bottom
R241 "HVC1206T5005JET" RESC3216N 119.1,-1 r270 bottom
R242 "HVC1206T5005JET" RESC3216N 104.15,0 r0 bottom
R243 "ERJ-1GNF-1002C" RESC0603 41.65,2.35 r270 top
R244 "ERJ-2GEJ392X" resc1005n 99.9,-7.6 r180 bottom
R245 "ERJ-2GEJ392X" resc1005n 96.2,-11.3 r0 bottom
R246 "ERJ-2GEJ392X" resc1005n 99.9,-9.8 r180 bottom
RT1 "NTCG063UH103HTBX" RESC0603 47.95,2.1 r270 top
RT2 "NTCG063UH103HTBX" RESC0603 84.8,0.95 r90 bottom
TP1 "1V2A" testpoint 12.5,-10.9 r180 top
TP2 "1V2B" testpoint 59.7,-7.9 r180 top
TP3 "1V2C" testpoint 73.5,12.5 r180 top
TP4 "1V2D" testpoint 102.9,-10.6 r180 top
TP5 "LV_RB" testpoint 36.8,-9.55 r180 top
TP6 "1V2_RB" testpoint 35.4,10.7 r180 top
TP7 "1V5A" testpoint 87.55,-10.5 r180 top
TP8 "1V4D" testpoint 92.4,-10.6 r180 top
TP9 "RX" testpoint 42.3,-2.5 r180 top
TP10 "TX" testpoint 42.25,7.25 r270 top
TP11 "1V0A" testpoint 11.5,11.6 r270 top
TP15 "I_1V5" testpoint 78.9,6.2 r270 top
TP16 "I_RX" testpoint 39.6,-7.3 r270 top
TP17 "I_TX" testpoint 39.6,2.4 r270 top

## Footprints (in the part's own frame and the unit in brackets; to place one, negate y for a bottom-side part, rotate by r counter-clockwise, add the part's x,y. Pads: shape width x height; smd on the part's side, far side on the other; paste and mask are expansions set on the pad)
BGA196C80P14X14_1200X1200X170 [mm] "BGA, 0.80mm Pitch, Square; 196 Pin, 14 Columns X 14 Rows, 12.00mm X 12.00mm X 1.70mm H"
  round 0.4 smd: A1(0,0) A2(0.8,0) A3(1.6,0) A4(2.4,0) A5(3.2,0) A6(4,0) A7(4.8,0) A8(5.6,0) A9(6.4,0) A10(7.2,0) A11(8,0) A12(8.8,0) A13(9.6,0) A14(10.4,0) B1(0,-0.8) B2(0.8,-0.8) B3(1.6,-0.8) B4(2.4,-0.8) B5(3.2,-0.8) B6(4,-0.8) B7(4.8,-0.8) B8(5.6,-0.8) B9(6.4,-0.8) B10(7.2,-0.8) B11(8,-0.8) B12(8.8,-0.8) B13(9.6,-0.8) B14(10.4,-0.8) C1(0,-1.6) C2(0.8,-1.6) C3(1.6,-1.6) C4(2.4,-1.6) C5(3.2,-1.6) C6(4,-1.6) C7(4.8,-1.6) C8(5.6,-1.6) C9(6.4,-1.6) C10(7.2,-1.6) C11(8,-1.6) C12(8.8,-1.6) C13(9.6,-1.6) C14(10.4,-1.6) D1(0,-2.4) D2(0.8,-2.4) D3(1.6,-2.4) D12(8.8,-2.4) D13(9.6,-2.4) D14(10.4,-2.4) E1(0,-3.2) E2(0.8,-3.2) E3(1.6,-3.2) E12(8.8,-3.2) E13(9.6,-3.2) E14(10.4,-3.2) F1(0,-4) F2(0.8,-4) F3(1.6,-4) F12(8.8,-4) F13(9.6,-4) F14(10.4,-4) G1(0,-4.8) G2(0.8,-4.8) G3(1.6,-4.8) G4(2.4,-4.8) H1(0,-5.6) H2(0.8,-5.6) H3(1.6,-5.6) H4(2.4,-5.6) J1(0,-6.4) J2(0.8,-6.4) J3(1.6,-6.4) J4(2.4,-6.4) J13(9.6,-6.4) J14(10.4,-6.4) K1(0,-7.2) K2(0.8,-7.2) K3(1.6,-7.2) K13(9.6,-7.2) K14(10.4,-7.2) L1(0,-8) L2(0.8,-8) L3(1.6,-8) L13(9.6,-8) L14(10.4,-8) M1(0,-8.8) M2(0.8,-8.8) M3(1.6,-8.8) M4(2.4,-8.8) M5(3.2,-8.8) M6(4,-8.8) M7(4.8,-8.8) M8(5.6,-8.8) M9(6.4,-8.8) M10(7.2,-8.8) M11(8,-8.8) M12(8.8,-8.8) M14(10.4,-8.8) N1(0,-9.6) N2(0.8,-9.6) N3(1.6,-9.6) N4(2.4,-9.6) N5(3.2,-9.6) N6(4,-9.6) N7(4.8,-9.6) N8(5.6,-9.6) N9(6.4,-9.6) N10(7.2,-9.6) N11(8,-9.6) N12(8.8,-9.6) N13(9.6,-9.6) N14(10.4,-9.6) P1(0,-10.4) P2(0.8,-10.4) P3(1.6,-10.4) P4(2.4,-10.4) P5(3.2,-10.4) P6(4,-10.4) P7(4.8,-10.4) P8(5.6,-10.4) P9(6.4,-10.4) P10(7.2,-10.4) P11(8,-10.4) P12(8.8,-10.4) P13(9.6,-10.4) P14(10.4,-10.4)
  round 0.4 smd mask+0.051: D4(2.4,-2.4) D5(3.2,-2.4) D6(4,-2.4) D7(4.8,-2.4) D8(5.6,-2.4) D9(6.4,-2.4) D10(7.2,-2.4) D11(8,-2.4) E4(2.4,-3.2) E5(3.2,-3.2) E6(4,-3.2) E7(4.8,-3.2) E8(5.6,-3.2) E9(6.4,-3.2) E10(7.2,-3.2) E11(8,-3.2) F4(2.4,-4) F5(3.2,-4) F6(4,-4) F7(4.8,-4) F8(5.6,-4) F9(6.4,-4) F10(7.2,-4) F11(8,-4) G5(3.2,-4.8) G6(4,-4.8) G7(4.8,-4.8) G8(5.6,-4.8) G9(6.4,-4.8) G10(7.2,-4.8) G11(8,-4.8) G12(8.8,-4.8) G13(9.6,-4.8) G14(10.4,-4.8) H5(3.2,-5.6) H6(4,-5.6) H7(4.8,-5.6) H8(5.6,-5.6) H9(6.4,-5.6) H10(7.2,-5.6) H11(8,-5.6) H12(8.8,-5.6) H13(9.6,-5.6) H14(10.4,-5.6) J5(3.2,-6.4) J6(4,-6.4) J7(4.8,-6.4) J8(5.6,-6.4) J9(6.4,-6.4) J10(7.2,-6.4) J11(8,-6.4) J12(8.8,-6.4) K4(2.4,-7.2) K5(3.2,-7.2) K6(4,-7.2) K7(4.8,-7.2) K8(5.6,-7.2) K9(6.4,-7.2) K10(7.2,-7.2) K11(8,-7.2) K12(8.8,-7.2) L4(2.4,-8) L5(3.2,-8) L6(4,-8) L7(4.8,-8) L8(5.6,-8) L9(6.4,-8) L10(7.2,-8) L11(8,-8) L12(8.8,-8) M13(9.6,-8.8)
  silkscreen extent -0.8,-11.2 11.2,0.8, body extent -0.8,-11.2 11.2,0.8, height 1.7
BGA289X17 [mm]
  round 0.27 smd: A1(0,0) A2(0.5,0) A3(1,0) A4(1.5,0) A5(2,0) A6(2.5,0) A7(3,0) A8(3.5,0) A9(4,0) A10(4.5,0) A11(5,0) A12(5.5,0) A13(6,0) A14(6.5,0) A15(7,0) A16(7.5,0) A17(8,0) B1(0,-0.5) B2(0.5,-0.5) B3(1,-0.5) B4(1.5,-0.5) B5(2,-0.5) B6(2.5,-0.5) B7(3,-0.5) B8(3.5,-0.5) B9(4,-0.5) B10(4.5,-0.5) B11(5,-0.5) B12(5.5,-0.5) B13(6,-0.5) B14(6.5,-0.5) B15(7,-0.5) B16(7.5,-0.5) B17(8,-0.5) C1(0,-1) C2(0.5,-1) C3(1,-1) C4(1.5,-1) C5(2,-1) C6(2.5,-1) C7(3,-1) C8(3.5,-1) C9(4,-1) C10(4.5,-1) C11(5,-1) C12(5.5,-1) C13(6,-1) C14(6.5,-1) C15(7,-1) C16(7.5,-1) C17(8,-1) D1(0,-1.5) D2(0.5,-1.5) D3(1,-1.5) D4(1.5,-1.5) D5(2,-1.5) D6(2.5,-1.5) D7(3,-1.5) D8(3.5,-1.5) D9(4,-1.5) D10(4.5,-1.5) D11(5,-1.5) D12(5.5,-1.5) D13(6,-1.5) D14(6.5,-1.5) D15(7,-1.5) D16(7.5,-1.5) D17(8,-1.5) E1(0,-2) E2(0.5,-2) E3(1,-2) E4(1.5,-2) E5(2,-2) E6(2.5,-2) E7(3,-2) E8(3.5,-2) E9(4,-2) E10(4.5,-2) E11(5,-2) E12(5.5,-2) E13(6,-2) E14(6.5,-2) E15(7,-2) E16(7.5,-2) E17(8,-2) F1(0,-2.5) F2(0.5,-2.5) F3(1,-2.5) F4(1.5,-2.5) F5(2,-2.5) F6(2.5,-2.5) F7(3,-2.5) F8(3.5,-2.5) F9(4,-2.5) F10(4.5,-2.5) F11(5,-2.5) F12(5.5,-2.5) F13(6,-2.5) F14(6.5,-2.5) F15(7,-2.5) F16(7.5,-2.5) F17(8,-2.5) G1(0,-3) G2(0.5,-3) G3(1,-3) G4(1.5,-3) G5(2,-3) G6(2.5,-3) G7(3,-3) G8(3.5,-3) G9(4,-3) G10(4.5,-3) G11(5,-3) G12(5.5,-3) G13(6,-3) G14(6.5,-3) G15(7,-3) G16(7.5,-3) G17(8,-3) H1(0,-3.5) H2(0.5,-3.5) H3(1,-3.5) H4(1.5,-3.5) H5(2,-3.5) H6(2.5,-3.5) H7(3,-3.5) H8(3.5,-3.5) H9(4,-3.5) H10(4.5,-3.5) H11(5,-3.5) H12(5.5,-3.5) H13(6,-3.5) H14(6.5,-3.5) H15(7,-3.5) H16(7.5,-3.5) H17(8,-3.5) J1(0,-4) J2(0.5,-4) J3(1,-4) J4(1.5,-4) J5(2,-4) J6(2.5,-4) J7(3,-4) J8(3.5,-4) J9(4,-4) J10(4.5,-4) J11(5,-4) J12(5.5,-4) J13(6,-4) J14(6.5,-4) J15(7,-4) J16(7.5,-4) J17(8,-4) K1(0,-4.5) K2(0.5,-4.5) K3(1,-4.5) K4(1.5,-4.5) K5(2,-4.5) K6(2.5,-4.5) K7(3,-4.5) K8(3.5,-4.5) K9(4,-4.5) K10(4.5,-4.5) K11(5,-4.5) K12(5.5,-4.5) K13(6,-4.5) K14(6.5,-4.5) K15(7,-4.5) K16(7.5,-4.5) K17(8,-4.5) L1(0,-5) L2(0.5,-5) L3(1,-5) L4(1.5,-5) L5(2,-5) L6(2.5,-5) L7(3,-5) L8(3.5,-5) L9(4,-5) L10(4.5,-5) L11(5,-5) L12(5.5,-5) L13(6,-5) L14(6.5,-5) L15(7,-5) L16(7.5,-5) L17(8,-5) M1(0,-5.5) M2(0.5,-5.5) M3(1,-5.5) M4(1.5,-5.5) M5(2,-5.5) M6(2.5,-5.5) M7(3,-5.5) M8(3.5,-5.5) M9(4,-5.5) M10(4.5,-5.5) M11(5,-5.5) M12(5.5,-5.5) M13(6,-5.5) M14(6.5,-5.5) M15(7,-5.5) M16(7.5,-5.5) M17(8,-5.5) N1(0,-6) N2(0.5,-6) N3(1,-6) N4(1.5,-6) N5(2,-6) N6(2.5,-6) N7(3,-6) N8(3.5,-6) N9(4,-6) N10(4.5,-6) N11(5,-6) N12(5.5,-6) N13(6,-6) N14(6.5,-6) N15(7,-6) N16(7.5,-6) N17(8,-6) P1(0,-6.5) P2(0.5,-6.5) P3(1,-6.5) P4(1.5,-6.5) P5(2,-6.5) P6(2.5,-6.5) P7(3,-6.5) P8(3.5,-6.5) P9(4,-6.5) P10(4.5,-6.5) P11(5,-6.5) P12(5.5,-6.5) P13(6,-6.5) P14(6.5,-6.5) P15(7,-6.5) P16(7.5,-6.5) P17(8,-6.5) R1(0,-7) R2(0.5,-7) R3(1,-7) R4(1.5,-7) R5(2,-7) R6(2.5,-7) R7(3,-7) R8(3.5,-7) R9(4,-7) R10(4.5,-7) R11(5,-7) R12(5.5,-7) R13(6,-7) R14(6.5,-7) R15(7,-7) R16(7.5,-7) R17(8,-7) T1(0,-7.5) T2(0.5,-7.5) T3(1,-7.5) T4(1.5,-7.5) T5(2,-7.5) T6(2.5,-7.5) T7(3,-7.5) T8(3.5,-7.5) T9(4,-7.5) T10(4.5,-7.5) T11(5,-7.5) T12(5.5,-7.5) T13(6,-7.5) T14(6.5,-7.5) T15(7,-7.5) T16(7.5,-7.5) T17(8,-7.5) U1(0,-8) U2(0.5,-8) U3(1,-8) U4(1.5,-8) U5(2,-8) U6(2.5,-8) U7(3,-8) U8(3.5,-8) U9(4,-8) U10(4.5,-8) U11(5,-8) U12(5.5,-8) U13(6,-8) U14(6.5,-8) U15(7,-8) U16(7.5,-8) U17(8,-8)
  silkscreen extent -0.5,-8.5 8.5,0.5, body extent -0.5,-8.5 8.5,0.5, height 1.3
CAPC0603N [mm] "Chip Capacitor, 2-Leads, Body 0.60x0.30mm, IPC Medium Density"
  rect 0.52x0.42 smd: 1(-0.31,0) 2(0.31,0)
  body extent -0.32,-0.17 0.32,0.17, height 0.3
capc1005n [mm] "Chip Capacitor, Body 1.0x0.5mm, IPC Medium Density"
  rect 0.8x0.6 smd: 1(-0.6,0) 2(0.6,0)
  silkscreen extent -1.3,-0.2 -1.3,0.2, body extent -0.55,-0.3 0.55,0.3, height 0.6
CAPC1005N [mm] "Chip Capacitor, Body 1.0x0.5mm, IPC Medium Density"
  rect 0.8x0.6 smd: 1(-0.6,0) 2(0.6,0)
  silkscreen extent -1.3,-0.2 -1.3,0.2, body extent -0.55,-0.3 0.55,0.3, height 0.6
CAPC1608N [mm] "Chip Capacitor, Body 1.6x0.8mm, IPC Medium Density"
  rect 1x1 smd: 1(-0.8,0) 2(0.8,0)
  silkscreen extent -1.6,-0.4 -1.6,0.4, body extent -0.87,-0.48 0.87,0.48, height 0.55
capc2012n [mm] "Chip Capacitor, Body 2.0x1.3mm, IPC Medium Density"
  rect 1.3x1.5 smd: 1(-0.85,0) 2(0.85,0)
  silkscreen extent -1.8,-0.65 -1.8,0.65, body extent -1.1,-0.72 1.1,0.72, height 1.1
cnc10 [mm]
  rect 1.2x4.75 smd: 1(0,0) 2(0,5.75) 3(2.54,0) 4(2.54,5.75) 5(5.08,0) 6(5.08,5.75) 7(7.62,0) 8(7.62,5.75) 9(10.16,0) 10(10.16,5.75)
  silkscreen extent -5.1,-3.88 15.24,8.2, body extent -5.08,-2.54 15.24,8.2, height 10
cnc14 [mm]
  rect 1.2x4.75 smd: 1(0,0) 2(0,5.75) 3(2.54,0) 4(2.54,5.75) 5(5.08,0) 6(5.08,5.75) 7(7.62,0) 8(7.62,5.75) 9(10.16,0) 10(10.16,5.75) 11(12.7,0) 12(12.7,5.75) 13(15.24,0) 14(15.24,5.75)
  silkscreen extent -5.1,-3.88 20.3,8.2, body extent -5.08,-2.54 20.32,8.2, height 10
CONTACT [mm]
  rect 1.85x0.9 smd: 1(0,0)
  silkscreen extent -2,-0.6 1.2,0.6, body extent -1.92,-0.5 1.34,0.5, height 1.24
DF57-2 [mm]
  rect 0.6x0.85 smd: 1(0,0) 2(1.2,0)
  rect 0.7x0.8 smd: 3(2.35,3.775) 4(-1.15,3.775)
  silkscreen extent -1.5,-0.4 2.7,3, body extent -1.5,0 2.7,3.8, height 1.6
DF57-3 [mm]
  rect 0.6x0.85 smd: 1(0,0) 2(1.2,0) 3(2.4,0)
  rect 0.7x0.8 smd: 4(3.55,3.775) 5(-1.15,3.775)
  silkscreen extent -1.5,-0.4 3.9,3, body extent -1.5,-0.25 3.9,4, height 1.6
JMP2PCB#1 [mm]
  round 0.2 smd paste-1 mask-1: 1(0,-0.5) 2(0,0.45)
  oval 1.4x1.8 on Bottom Solder paste-1 mask-1: 9(0,0)
  Top Layer lines w0.254: -0.25,-0.45 -0.166,-0.45 ; 0.25,-0.45 0.166,-0.45 ; -0.3,0.2 cw(c0,0.2) 0.3,0.2 ; -0.25,0.45 0.25,0.45 ; -0.166,-0.45 ccw(c0,-0.2) 0,-0.5 ccw(c0,-0.2) 0.166,-0.45 ; -0.166,-0.45 cw(c0,-0.2) -0.3,-0.2 ; -0.166,-0.45 0,-0.45 0.166,-0.45 ; 0.166,-0.45 ccw(c0,-0.2) 0.3,-0.2 ; -0.3,-0.2 0.3,-0.2 ; -0.3,-0.2 -0.5,-0.2 ccw(c0,-0.2) -0.433,-0.45 ccw(c0,-0.2) 0.05,-0.697 ccw(c0,-0.2) 0.477,-0.35 ccw(c0,-0.2) 0.5,-0.2 0.3,-0.2 ; -0.5,0.2 cw(c0,0.2) 0.5,0.2 -0.5,0.2
JMP2PCB#2 [mm]
  round 0.2 smd paste-1 mask-1: 1(0,-0.5) 2(0,0.45)
  oval 1.4x1.8 on Bottom Solder paste-1 mask-1: 9(0,0)
  Top Layer lines w0.254: -0.25,-0.45 -0.166,-0.45 ; 0.25,-0.45 0.166,-0.45 ; -0.3,0.2 cw(c0,0.2) -0.166,0.45 ; 0.3,0.2 ccw(c0,0.2) 0.166,0.45 ; -0.25,0.45 -0.166,0.45 ; 0.25,0.45 0.166,0.45 ; -0.166,-0.45 ccw(c0,-0.2) 0,-0.5 ccw(c0,-0.2) 0.166,-0.45 ; -0.166,-0.45 cw(c0,-0.2) -0.3,-0.2 ; -0.166,-0.45 0,-0.45 0.166,-0.45 ; 0.166,-0.45 ccw(c0,-0.2) 0.3,-0.2 ; -0.3,-0.2 -0.5,-0.2 ccw(c0,-0.2) -0.433,-0.45 ccw(c0,-0.2) 0.05,-0.697 ccw(c0,-0.2) 0.5,-0.2 0.3,-0.2 ; -0.3,-0.2 0.3,-0.2 ; -0.166,0.45 cw(c0,0.2) 0.166,0.45 ; -0.166,0.45 0,0.45 0.166,0.45 ; -0.5,0.2 cw(c0,0.2) 0.166,0.672 cw(c0,0.2) 0.5,0.2 -0.5,0.2
LED_RED [mm] "LTST-C194KRKT"
  rect 0.8x0.8 smd: 1(0,0) 2(1.5,0)
  body extent -0.1,-0.45 1.6,0.45, height 0.6
RESC0603 [mm]
  rect 0.35x0.4 smd: 1(0,0) 2(0.65,0)
  body extent 0,-0.15 0.65,0.15, height 0.5
resc0603 [mm]
  rect 0.35x0.4 smd: 1(0,0) 2(0.65,0)
  body extent 0,-0.15 0.65,0.15, height 0.5
resc1005n [mm] "Chip Resistor, Body 1.1x0.5mm, IPC Medium Density"
  rect 0.8x0.7 smd: 1(-0.6,0) 2(0.6,0)
  body extent -0.55,-0.3 0.55,0.3, height 0.4
RESC3216N [mm] "Chip Resistor, Body 3.2x1.6mm, IPC Medium Density"
  rect 1.3x1.8 smd: 1(-1.45,0) 2(1.45,0)
  silkscreen extent -0.4,-0.8 0.4,0.8, body extent -1.68,-0.87 1.68,0.87, height 0.55
SOT-23 [mm]
  rect 0.6x1.25 smd: 1(0,0) 2(1.9,0) 3(0.95,2)
  silkscreen extent 0,0 1.9,2, body extent 0,0.3 1.9,1.7, height 1.2
testpoint [mil]
  round 40 smd paste-39.37: 1(0,0)
  silkscreen extent -39,-39 39,39
VENKEL0805 [mm]
  rect 1.1x1.2 smd: 1(0,0) 2(1.9,0)
  body extent -0.75,-0.8 2.65,0.8, height 1.7
VTRX+ [mm]
  rect 0.2x1.12 smd: 1(0,0) 2(0,2.66) 3(0.4,0) 4(0.4,2.66) 5(0.8,0) 6(0.8,2.66) 7(1.2,0) 8(1.2,2.66) 9(1.6,0) 10(1.6,2.66) 11(2,0) 12(2,2.66) 13(2.4,0) 14(2.4,2.66) 15(2.8,0) 16(2.8,2.66) 17(3.2,0) 18(3.2,2.66) 19(3.6,0) 20(3.6,2.66) 21(4,0) 22(4,2.66) 23(4.4,0) 24(4.4,2.66) 25(4.8,0) 26(4.8,2.66) 27(5.2,0) 28(5.2,2.66) 29(5.6,0) 30(5.6,2.66) 31(6,0) 32(6,2.66) 33(6.4,0) 34(6.4,2.66) 35(6.8,0) 36(6.8,2.66) 37(7.2,0) 38(7.2,2.66) 39(7.6,0) 40(7.6,2.66)
  silkscreen extent -1.2,-2.6 8.8,17.4, body extent -1.2,-2.6 8.8,17.4, height 2
WDFNX208 [mm]
  rect 0.3x0.5 smd: 1(0,0) 2(0.5,0) 3(1,0) 4(1.5,0) 5(1.5,1.8) 6(1,1.8) 7(0.5,1.8) 8(0,1.8)
  rect 1.6x0.9 smd: 9(0.75,0.9)
  silkscreen extent -0.57,-0.07 1.73,1.35, body extent -0.25,-0.12 1.75,1.87, height 0.8
WP7B-40P [mm]
  rect 0.22x0.55 smd: 1(0,0) 2(0.4,0) 3(0.8,0) 4(1.2,0) 5(1.6,0) 6(2,0) 7(2.4,0) 8(2.8,0) 9(3.2,0) 10(3.6,0) 11(4,0) 12(4.4,0) 13(4.8,0) 14(5.2,0) 15(5.6,0) 16(6,0) 17(6.4,0) 18(6.8,0) 19(7.2,0) 20(7.6,0) 21(7.6,1.85) 22(7.2,1.85) 23(6.8,1.85) 24(6.4,1.85) 25(6,1.85) 26(5.6,1.85) 27(5.2,1.85) 28(4.8,1.85) 29(4.4,1.85) 30(4,1.85) 31(3.6,1.85) 32(3.2,1.85) 33(2.8,1.85) 34(2.4,1.85) 35(2,1.85) 36(1.6,1.85) 37(1.2,1.85) 38(0.8,1.85) 39(0.4,1.85) 40(0,1.85) 41(-0.4,0) 42(8,0) 43(8,1.85) 44(-0.4,1.85)
  silkscreen extent -0.65,-1 8.25,2.3, body extent -1.5,-0.32 9.1,2.17, height 0.5

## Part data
C105 C106 C107 C108 C109 C111 C112 C113 C114 C115 C116 C117 C118 C119 C120 C121 C122 C123 C124 C125 C126 C127 C128 C129 C130 C131 C132 C133 C134 C135 C136 C138 C139 C140 C141 C150 C151 C152 C153 C154 C155 C160 C162 C163 C164 C165 C166 C167 C168 C169 C201 C202 C203 C204 C205 C206 C207 C208 C209 C210 C211 C212 C213 C214 C215 C216 C217 C218 C219 C220 C221 C222 C223 C224 C225 C226 C227 C228 C229 C230 C231 C232 C233: library part C, "CERAMIC CAPACITOR"
CT1 CT2 CT3: library part CONTACT
D1: library part LED2, "Typical RED, GREEN, YELLOW, AMBER GaAs LED"
IC1 IC4: "Low Power Gigabit Transceiver", Case=BGA289, Manufacturer=CERN
IC2: library part VTRX+_DF40C-2.0-40DS-0.4V, "VTRX+ module with 2.5mm stack Height."
IC3: library part "CERN_GBT-SCA_REV 6.2", "The Slow Control Adapter ASIC for the GBT System"
JMP1 JMP2: library part JMP2, "printed on PCB"
P1: library part "Header 5X2", "Header, 5-Pin, Dual row"
P2 P3 P11 P14 P15: library part "Header 7X2", "Header, 7-Pin, Dual row"
P4 P16 P17: library part "Header 4", "Header, 4-Pin"
P5 P6 P7 P8 P9 P10: library part WP7B-40P, "plug"
P12: library part "Header 5", "Header, 5-Pin"
Q1: library part NPN, "NPN Bipolar Transistor"
R101 R102 R103 R104 R105 R106 R107 R109 R110 R111 R112 R113 R114 R115 R116 R117 R118 R119 R120 R122 R123 R124 R125 R126 R127 R128 R129 R130 R131 R132 R133 R134 R135 R141 R142 R143 R144 R145 R146 R147 R148 R201 R202 R203 R204 R205 R206 R207 R208 R209 R210 R211 R213 R214 R215 R216 R217 R218 R219 R220 R221 R222 R223 R224 R225 R226 R227 R228 R229 R230 R231 R232 R233 R234 R235 R236 R237 R238 R239 R240 R241 R242 R243 R244 R245 R246: library part R1, "FILM RESISTOR"
RT1 RT2: library part "Res Thermal", "Thermistor"
TP1 TP2 TP3 TP4 TP5 TP6 TP7 TP8 TP9 TP10 TP11 TP15 TP16 TP17: library part TP, "TEST POINT 40MIL DIA."

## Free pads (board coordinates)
  round 0.4 hole 0.25 mask+0.051: 1(11.25,0) 1(25.7,3.6) 1(25.8,-8.4) 1(26.7,-6.8) 1(27.45,0.6) 1(27.45,1.8) 1(27.5,-3) 1(27.5,-1.8) 1(27.6,-1) 1(27.6,-0.35) 1(27.6,2.8) 1(28,-1.4) 1(28.4,-7.2) 1(28.4,-3.8) 1(28.4,-3) 1(28.4,-1.8) 1(28.5,-0.6) 1(28.5,0.6) 1(28.5,1.8) 1(28.5,3) 1(29,-8.4) 1(61.875,-5.875) 1(62.875,-5.875) 1(65.6,0.9) 1(68.6,3) 1(68.9,6.9) 1(69.1,2.5) 1(69.6,-1.8) 1(70,-3.75) 1(105.531,5.569) 1(110.2,-1.3) 1(114,6.5) 1(117.9,-2.4) 1(119.1,9.2) 1(119.1,6.4) 1(125.9,-2.4) 1(127.1,9.2) 1(127.1,6.3)
  round 0.25 / inner round 0.35 / far side round 0.35 hole 0.15 mask+0.051: 1(51.35,2.9) 1(51.75,1.75) 1(51.75,-0.25) 1(52.25,-1.75) 1(52.25,-1.25) 1(52.25,-0.75) 1(52.25,0.25) 1(52.25,0.75) 1(52.25,1.25) 1(52.25,-0.25) 1(52.75,-1.75) 1(52.75,-0.75) 1(52.75,-1.25) 1(52.75,-0.25) 1(52.75,1.25) 1(52.75,2.25) 1(52.75,3.25) 1(53.25,0.25) 1(53.25,1.25) 1(53.25,-0.75) 1(53.25,-0.25) 1(53.25,0.75) 1(53.25,3.25) 1(53.25,-1.75) 1(53.25,-1.25) 1(53.25,2.25) 1(53.25,-3.25) 1(53.25,-2.75) 1(53.5,-4.4) 1(53.75,-3.75) 1(53.75,0.75) 1(53.75,1.25) 1(53.75,-2.75) 1(53.75,2.25) 1(53.75,2.75) 1(54.25,-3.25) 1(54.25,-2.75) 1(54.25,-0.25) 1(54.25,-1.75) 1(54.25,-0.75) 1(54.25,3.25) 1(54.25,0.25) 1(54.251,1.226) 1(54.275,2.25) 1(54.75,0.25) 1(54.75,0.75) 1(54.75,1.25) 1(54.75,-0.75) 1(54.75,-0.25) 1(54.775,2.25) 1(55.25,-3.25) 1(55.25,-2.75) 1(55.25,-0.75) 1(55.25,0.25) 1(55.25,0.75) 1(55.25,1.25) 1(55.25,-1.75) 1(55.25,-0.25) 1(55.25,-1.25) 1(55.75,2.75) 1(55.75,3.25) 1(55.75,-3.75) 1(55.75,-0.75) 1(55.75,0.25) 1(55.75,0.75) 1(55.75,1.25) 1(55.75,-0.25) 1(55.75,-4.25) 1(55.75,-2.75) 1(56.25,-0.25) 1(56.25,-1.75) 1(56.25,-1.25) 1(56.25,2.75) 1(56.25,-3.25) 1(56.25,-2.75) 1(56.5,-4.4) 1(56.75,2.75) 1(56.75,3.25) 1(56.75,-0.25) 1(56.75,-3.75) 1(56.75,0.75) 1(56.75,1.25) 1(56.75,-1.25) 1(57.25,0.75) 1(57.25,1.25) 1(57.25,-0.25) 1(57.25,-2.75) 1(57.25,-0.75) 1(57.25,2.75) 1(57.75,2.75) 1(57.75,3.25) 1(57.75,-3.25) 1(57.75,-2.75) 1(57.75,-0.25) 1(57.75,0.75) 1(57.75,1.25) 1(57.75,-1.75) 1(57.75,-1.25) 1(57.75,-0.75) 1(58.25,0.25) 1(58.25,0.75) 1(58.25,1.25) 1(58.25,-0.75) 1(58.25,-1.25) 1(58.25,-1.75) 1(58.25,-0.25) 1(58.25,2.75) 1(58.25,3.25) 1(58.75,-3.25) 1(58.75,-2.75) 1(58.75,-1.75) 1(58.75,2.75) 1(58.75,3.25) 1(58.75,3.75) 1(58.752,4.25) 1(59.248,-3.771) 1(59.248,3.238) 1(59.25,2.75) 1(59.25,-3.25) 1(59.25,-1.75) 1(59.25,-1.25) 1(59.25,-0.75) 1(59.25,-0.25) 1(59.25,0.25) 1(59.25,3.75) 1(59.25,4.25) 1(59.75,-3.75) 1(59.75,-3.25) 1(59.75,3.25) 1(59.75,4.25) 1(59.75,-4.25) 1(59.75,-1.75) 1(59.75,-0.25) 1(59.75,3.75) 1(60.25,-3.25) 1(60.25,4.25) 1(60.25,3.25) 1(70.6,0.5) 1(70.6,1) 1(70.75,-1.75) 1(70.75,-0.75) 1(70.75,-0.25) 1(70.75,1.75) 1(71.25,-3.75) 1(71.25,-3.25) 1(71.25,-2.75) 1(71.25,0.75) 1(71.25,-1.75) 1(71.25,-0.75) 1(71.25,-0.25) 1(71.25,1.25) 1(71.25,1.75) 1(71.75,-0.25) 1(71.75,-3.75) 1(71.75,-2.75) 1(71.75,1.25) 1(71.75,1.75) 1(71.75,-3.25) 1(71.75,-1.75) 1(71.75,-0.75) 1(72.25,-0.25) 1(72.25,-2.75) 1(72.25,-1.75) 1(72.25,-1.25) 1(72.25,-0.75) 1(72.25,0.75) 1(72.25,2.25) 1(72.75,-3.25) 1(72.75,2.25) 1(72.75,1.25) 1(72.75,1.75) 1(72.75,-3.75) 1(73.25,-4.25) 1(73.25,-0.25) 1(73.25,-3.75) 1(73.25,-0.75) 1(73.25,0.25) 1(73.25,0.75) 1(73.75,-0.75) 1(73.75,-0.25) 1(73.75,-3.25) 1(73.75,0.25) 1(73.75,0.75) 1(73.75,1.25) 1(73.75,-3.75) 1(74.25,-4.25) 1(74.25,-0.25) 1(74.25,1.25) 1(74.25,3.75) 1(74.25,4.25) 1(74.25,-0.75) 1(74.255,-3.755) 1(74.75,-0.25) 1(74.75,0.25) 1(74.75,0.75) 1(74.75,1.25) 1(74.75,3.75) 1(74.75,-2.25) 1(74.75,-0.75) 1(74.75,3.25) 1(75.25,-0.75) 1(75.25,0.75) 1(75.25,1.25) 1(75.25,4.25) 1(75.25,-1.25) 1(75.25,0.25) 1(75.25,3.75) 1(75.75,0.75) 1(75.75,1.25) 1(75.75,3.75) 1(75.75,-3.25) 1(75.75,-2.75) 1(75.75,-1.25) 1(75.75,-0.75) 1(75.75,3.25) 1(75.75,-3.75) 1(76.25,-4.25) 1(76.25,0.25) 1(76.25,0.75) 1(76.25,1.25) 1(76.25,4.25) 1(76.25,-3.75) 1(76.25,3.75) 1(76.75,0.25) 1(76.75,0.75) 1(76.75,1.25) 1(76.75,3.75) 1(76.75,-3.75) 1(76.75,-3.25) 1(76.75,-2.75) 1(76.75,-1.25) 1(76.75,-0.75) 1(76.75,-0.25) 1(76.75,3.25) 1(77.25,-4.25) 1(77.25,0.25) 1(77.25,0.75) 1(77.25,4.25) 1(77.25,-3.75) 1(77.25,-1.25) 1(77.25,-0.75) 1(77.25,-0.25) 1(77.25,1.25) 1(77.25,3.75) 1(77.75,3.75) 1(77.75,-2.75) 1(77.75,1.75) 1(77.75,3.25) 1(78.25,-2.25) 1(78.25,-1.75) 1(78.25,0.75) 1(78.25,1.25) 1(78.25,1.75) 1(78.25,-2.75) 1(78.75,-1.75) 1(78.75,-2.25) 1(78.75,-1.25) 1(78.75,0.25) 1(78.75,0.75) 1(78.75,1.25) 1(78.75,1.75) 1(78.75,-2.75) 1(79.25,-1.25) 1(79.25,0.25)
  round 0.4 hole 0.25: 1(85.1,-2.45) 1(85.15,-0.85) 1(96.4,-3.2) 1(96.4,-4.8) 1(96.4,-4) 1(96.4,-2.4) 1(96.4,-1.6) 1(96.4,-0.8) 1(96.4,0.8) 1(96.4,1.6)
  round 0.48 hole 0.3: 1(85.2,-1.6) 1(85.2,3.2) 1(86,2.4) 1(86,0.8) 1(86.8,0.8) 1(86.8,2.4) 1(87.6,3.2) 1(88.4,-4.8) 1(88.4,-4) 1(89.2,-4.8) 1(89.2,-5.6) 1(90,-4.8) 1(90,-5.6)
  round 0.48 hole 0.3 mask+0.051: 1(86.8,-4) 1(87.6,-3.2) 1(87.6,-2.4) 1(87.6,-1.6) 1(87.6,-0.8) 1(87.6,0) 1(87.6,0.8) 1(88.4,0.8) 1(88.4,1.6) 1(88.4,2.4) 1(88.4,-0.8) 1(88.4,0) 1(88.4,-2.4) 1(88.4,-1.6) 1(89.2,-4) 1(89.2,-3.2) 1(89.2,1.6) 1(89.2,2.4) 1(89.2,-2.4) 1(89.2,-1.6) 1(89.2,-0.8) 1(89.2,0) 1(89.2,0.8) 1(90,0) 1(90,0.8) 1(90,-4) 1(90,1.6) 1(90,2.4) 1(90.8,-2.4) 1(90.8,-5.6) 1(90.8,-4.8) 1(90.8,-4) 1(90.8,-3.2) 1(90.8,2.4) 1(90.8,-1.6) 1(90.8,-0.8) 1(91.6,-2.4) 1(91.6,-5.6) 1(91.6,-4.8) 1(91.6,-4) 1(91.6,-3.2) 1(91.6,-1.6) 1(91.6,1.6) 1(91.6,2.4) 1(91.6,0) 1(91.6,0.8) 1(92.4,0.8) 1(92.4,1.6) 1(92.4,2.4) 1(92.4,3.2) 1(92.4,-2.4) 1(92.4,-1.6) 1(92.4,-0.8) 1(92.4,0) 1(92.4,4.8) 1(93.2,-3.2) 1(93.2,-2.4) 1(93.2,-1.6) 1(93.2,0) 1(93.2,0.8) 1(93.2,1.6) 1(93.2,2.4) 1(93.2,3.2) 1(93.2,4.8) 1(94,-3.2) 1(94,0) 1(94,0.8) 1(94,1.6) 1(94,2.4) 1(94,3.2) 1(94,-1.6) 1(94,-0.8)

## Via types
v1: diameter 0.4, hole 0.25, Top Layer to Bottom Layer, 914 vias

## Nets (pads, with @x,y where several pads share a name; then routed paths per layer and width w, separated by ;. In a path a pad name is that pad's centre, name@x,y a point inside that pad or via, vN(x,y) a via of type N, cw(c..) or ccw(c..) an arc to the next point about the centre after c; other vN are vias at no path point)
1V0A: P5.20 P7.20 P9.20 R201.1 TP11.1 | length 175.4
  Top Layer w0.102: TP11.1@11.5,11.6 14.4,8.7 v1(17.8,8.7) ; v1(43.25,2.1) R201.1@44.15,2.1
  M1 w0.102: v1(17.8,8.7) 20.4,6.1 33.8,6.1 37.8,2.1 v1(43.25,2.1) ; v1(57.9,15.573) 57.9,15.6 113.1,15.6 113.7,15 113.7,14.3 112,12.6 107.8,12.6 v1(105.5,10.3)
  Bottom Layer w0.102: P5.20@18.2,12 18.2,9.1 v1(17.8,8.7) 15.1,8.7 14.4,9.4 14.4,13.5 18.5,17.6 55.9,17.6 57.9,15.6 57.9,9.6 58.6,8.9 61.6,8.9 61.8,9.1 P7.20@61.8,12 ; P9.20@105.4,12 105.4,10.4 v1(105.5,10.3)
1V2_mon0: C201.2 IC3.P14 P5.17 pad.1@70,-3.75 R203.2 | length 84.5
  Top Layer w0.102: C201.2@82.8,-5.6 v1(83.7,-5.6) 85.2,-5.6 IC3.P14@85.6,-5.2
  M2 w0.102: pad.1@70,-3.75 71.35,-5.1 83.2,-5.1 v1(83.7,-5.6)
  Bottom Layer w0.102: P5.17@19.4,12 19.4,9.1 19.9,8.6 34.8,8.6 36,9.8 49.4,9.8 53.6,5.6 61.8,5.6 62.9,4.5 68.5,4.5 70,3 pad.1@70,-3.75 ; R203.2@82.8,-8.2 83.3,-8.2 83.7,-7.8 v1(83.7,-5.6)
1V2_mon1: C202.2 IC3.P13 P5.18 pad.1@69.6,-1.8 R205.2 | length 82.3
  Top Layer w0.102: v1(83.7,-5) 85,-5 IC3.P13@85.6,-4.4
  M2 w0.102: pad.1@69.6,-1.8 70.75,-2.95 70.75,-3.75 71.75,-4.75 83.45,-4.75 v1(83.7,-5)
  Bottom Layer w0.102: P5.18@19,12 19,9 19.8,8.2 35,8.2 36.3,9.5 49.1,9.5 53.3,5.3 61.3,5.3 62.4,4.2 68.2,4.2 69.6,2.8 pad.1@69.6,-1.8 ; R205.2@82.8,-6.9 C202.2@82.8,-5.6 83.1,-5.6 v1(83.7,-5)
1V2_mon2: C203.2 IC3.P12 P7.17 R207.2 | length 123.2
  Top Layer w0.102: C203.2@82.8,-4.4 v1(84.1,-4.4) 84.8,-4.4 IC3.P12@85.6,-3.6
  M2 w0.102: v1(55.9,12.2) 59.9,16.2 113.5,16.2 114.6,15.1 114.6,9.2 113.6,8.2 107.3,8.2 100.3,1.2 97.6,1.2 96,-0.4 96,-2 94.4,-3.6 85.6,-3.6 84.8,-4.4 v1(84.1,-4.4)
  Bottom Layer w0.102: v1(55.9,12.2) 55.9,9.8 57.7,8 62.1,8 63,8.9 P7.17@63,12 ; v1(84.1,-4.4) 84.3,-4.6 R207.2@84.3,-6.9
1V2_mon3: C204.2 IC3.P11 P7.18 R209.2 | length 120.6
  Top Layer w0.102: v1(84.6,-3.8) IC3.P11@85.6,-2.8
  M2 w0.102: v1(56.6,12.2) 60,15.6 113.4,15.6 114,15 114,9.6 113.2,8.8 107.262,8.8 101.762,3.3 97.5,3.3 95.6,1.4 95.6,-1.6 94.4,-2.8 85.6,-2.8 v1(84.6,-3.8)
  Bottom Layer w0.102: v1(56.6,12.2) 56.6,9.7 58,8.3 62,8.3 62.6,8.9 P7.18@62.6,12 ; C204.2@82.8,-4.4 83.2,-4.4 83.8,-3.8 v1(84.6,-3.8) 84.7,-3.9 84.7,-5.5 85.6,-6.4 R209.2@85.6,-6.9
1V2_mon4: C205.2 IC3.P10 P9.17 pad.1@85.1,-2.45 R211.2 | length 40.6
  Top Layer w0.102: C205.2@82.8,-3.2 84.35,-3.2 pad.1@85.1,-2.45 85.15,-2.45 IC3.P10@85.6,-2
  M2 w0.102: pad.1@85.1,-2.45 85.15,-2.45 85.6,-2 94.4,-2 95.2,-1.2 95.2,3.6 99.619,8.019 105.681,8.019 106.6,8.938 v1(106.6,10.3)
  Bottom Layer w0.102: pad.1@85.1,-2.45 85.1,-4.6 86.9,-6.4 R211.2@86.9,-6.9 ; v1(106.6,10.3) P9.17@106.6,12
1V2_mon5: C206.2 IC3.P9 P9.18 pad.1@85.2,-1.6 R213.2 | length 41.1
  Top Layer w0.13: pad.1@85.2,-1.6 IC3.P9@85.6,-1.2
  M2 w0.102: pad.1@85.2,-1.6 85.6,-1.2 94.4,-1.2 94.8,-0.8 94.8,4 99.681,8.881 105.619,8.881 106.2,9.462 v1(106.2,9.6)
  Bottom Layer w0.102: C206.2@82.8,-3.2 83.6,-3.2 pad.1@85.2,-1.6 85.6,-2 85.6,-3.8 88.2,-6.4 R213.2@88.2,-6.9 ; v1(106.2,9.6) P9.18@106.2,12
